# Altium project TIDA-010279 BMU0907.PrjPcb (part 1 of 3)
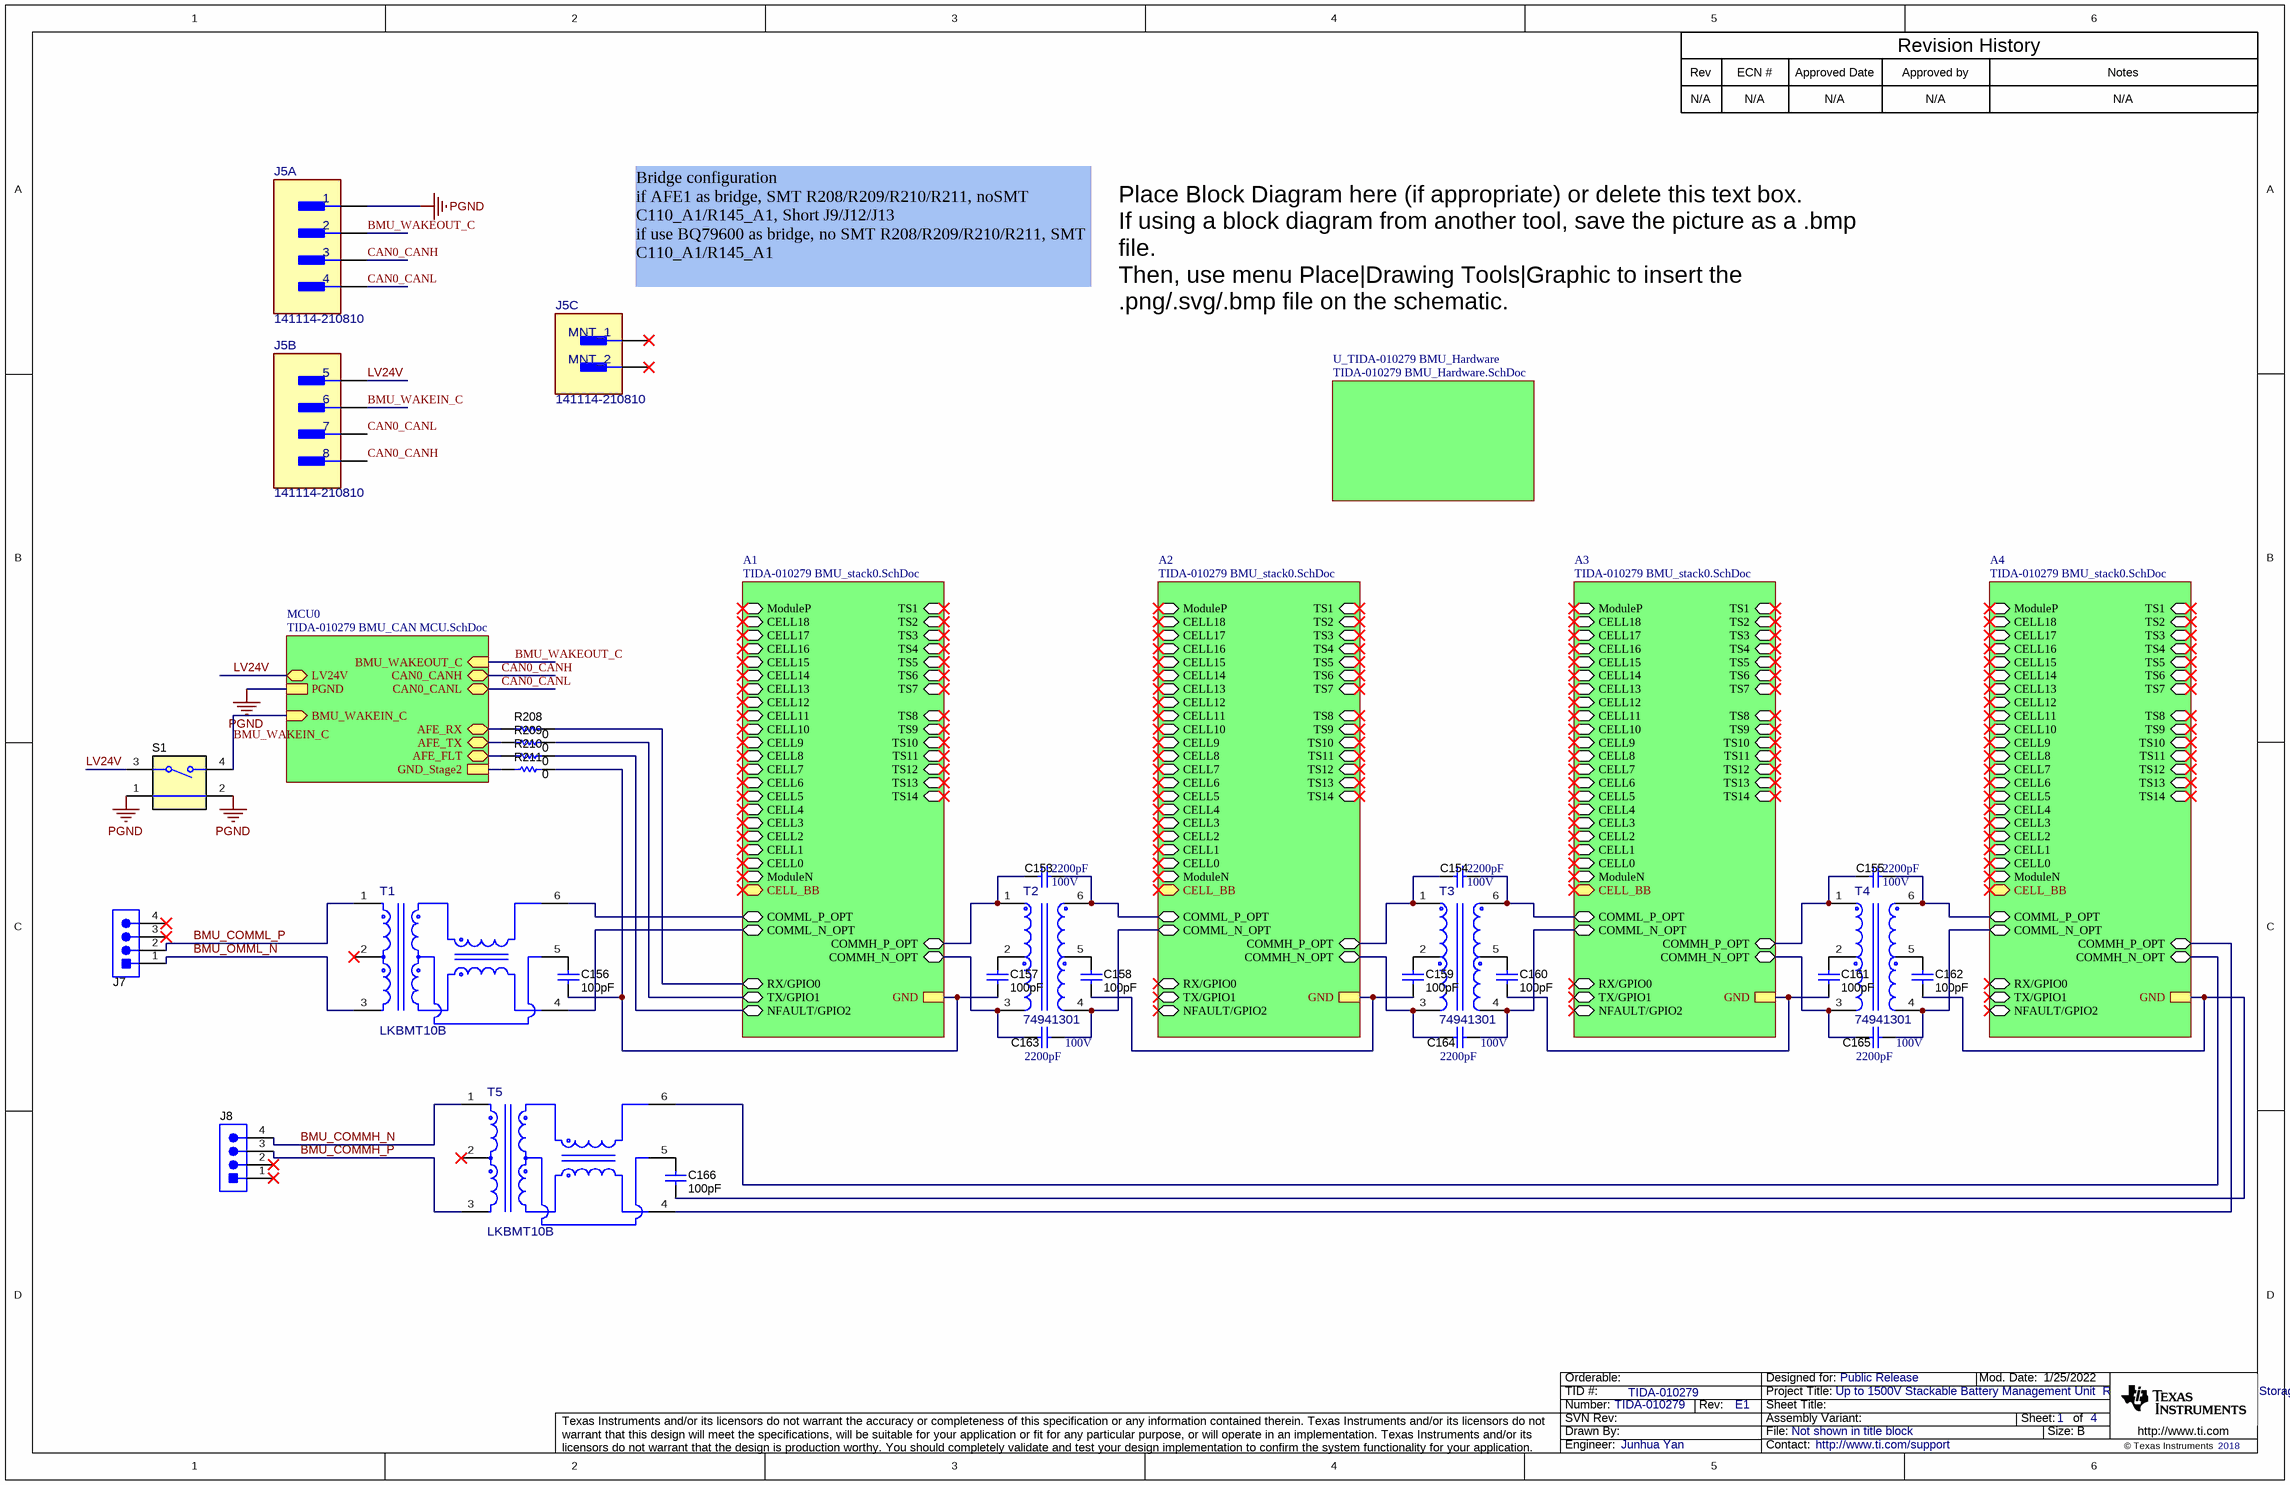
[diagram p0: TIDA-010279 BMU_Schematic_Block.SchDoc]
CopyrightYear: 2018; Orderable: N/A; PCB_Layout: Junhua Yan; PCB_Rev: E1; PRJ_Customer: Public Release; PRJ_Engineer: Junhua Yan; PRJ_Number: TIDA-010279; PRJ_Title: Up to 1500V Stackable Battery Management Unit  Reference Design for Energy Storage Systems; SCH_Rev: E1; TechSupport: http://www.ti.com/support; TID: TIDA-010279
4 sheets, 1494 parts. Net scope: hierarchical (ports join the sheet entries above them; power ports are global).
Board file: TIDA-010279 BMU0829.PcbDoc
Sheets:
  TIDA-010279 BMU_Schematic_Block.SchDoc
    A1 = TIDA-010279 BMU_stack0.SchDoc
    MCU0 = TIDA-010279 BMU_CAN MCU.SchDoc
    A2 = TIDA-010279 BMU_stack0.SchDoc
    A3 = TIDA-010279 BMU_stack0.SchDoc
    A4 = TIDA-010279 BMU_stack0.SchDoc
    U_TIDA-010279 BMU_Hardware = TIDA-010279 BMU_Hardware.SchDoc

## Sheet TIDA-010279 BMU_Schematic_Block.SchDoc
size 431 x 279 mm; Date: Not shown in title block; ApprovedBy: Not shown in title block; CheckedBy: Not shown in title block; Author: Not shown in title block; CompanyName: Not shown in title block; Engineer: Not shown in title block; Organization: Not shown in title block; Address1: Not shown in title block; Address2: Not shown in title block; Address3: Not shown in title block; Address4: Not shown in title block; DocumentNumber: 1; Revision: Use project parameter SCH_Rev; SheetNumber: 1; SheetTotal: 4; PageSetup: Record=PageOptions¦CenterHorizontal=True¦CenterVertical=True¦PrintScale=1.00¦XCorrection=1.00¦YCorrection=1.00¦PrintKind=0¦BorderSize=5000000¦LeftOffset=0¦BottomOffset=0¦Orientation=2¦PaperLength=1000¦PaperWidth=1000¦Scale=100¦PaperSource=15¦PrintQuality=600¦MediaType=1¦DitherType=10¦PaperKind=Letter¦PrintScaleMode=1

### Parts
C153  VDC_V: 100V  ValueDisplayed: 2200pF  [1206]  (hidden comment: 12061A222JAT2A)
C154  VDC_V: 100V  ValueDisplayed: 2200pF  [1206]  (hidden comment: 12061A222JAT2A)
C155  VDC_V: 100V  ValueDisplayed: 2200pF  [1206]  (hidden comment: 12061A222JAT2A)
C156  ValueDisplayed: 100pF  [0603]  (hidden comment: GCM1885C1H101JA16J)
C157  ValueDisplayed: 100pF  [0603]  (hidden comment: GCM1885C1H101JA16J)
C158  ValueDisplayed: 100pF  [0603]  (hidden comment: GCM1885C1H101JA16J)
C159  ValueDisplayed: 100pF  [0603]  (hidden comment: GCM1885C1H101JA16J)
C160  ValueDisplayed: 100pF  [0603]  (hidden comment: GCM1885C1H101JA16J)
C161  ValueDisplayed: 100pF  [0603]  (hidden comment: GCM1885C1H101JA16J)
C162  ValueDisplayed: 100pF  [0603]  (hidden comment: GCM1885C1H101JA16J)
C163  VDC_V: 100V  ValueDisplayed: 2200pF  [1206]  (hidden comment: 12061A222JAT2A)
C164  VDC_V: 100V  ValueDisplayed: 2200pF  [1206]  (hidden comment: 12061A222JAT2A)
C165  VDC_V: 100V  ValueDisplayed: 2200pF  [1206]  (hidden comment: 12061A222JAT2A)
C166  ValueDisplayed: 100pF  [0603]  (hidden comment: GCM1885C1H101JA16J)
J5  141114-210810  [FP-141114-210810_CONN_HDR16-MFG]  (parts A,B,C of 3)
J7  70551-0038  [Molex_70551-0038]  (value not drawn)
J8  70551-0038  [Molex_70551-0038]  (value not drawn)
R208  ValueDisplayed: 0  [0402]  (hidden comment: CRCW04020000Z0ED)
R209  ValueDisplayed: 0  [0402]  (hidden comment: CRCW04020000Z0ED)
R210  ValueDisplayed: 0  [0402]  (hidden comment: CRCW04020000Z0ED)
R211  ValueDisplayed: 0  [0402]  (hidden comment: CRCW04020000Z0ED)
S1  1188E-1K2-V-TR  [SW_1188E]  (value not drawn)
T1  LKBMT10B  [FP-LKBMT10B_SMT_XFRMR_27MM9_12MM5-MFG]
T2  74941301  [FP-HMU1228NL_SMT_TRANSFORMER_8MM89_10MM09-MFG]
T3  74941301  [FP-HMU1228NL_SMT_TRANSFORMER_8MM89_10MM09-MFG]
T4  74941301  [FP-HMU1228NL_SMT_TRANSFORMER_8MM89_10MM09-MFG]
T5  LKBMT10B  [FP-LKBMT10B_SMT_XFRMR_27MM9_12MM5-MFG]

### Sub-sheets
A1 = TIDA-010279 BMU_stack0.SchDoc: ModuleP (bidir), CELL9 (bidir), CELL10 (bidir), CELL11 (bidir), CELL12 (bidir), CELL13 (bidir), CELL14 (bidir), CELL15 (bidir), CELL16 (bidir), CELL8 (bidir), CELL17 (bidir), CELL18 (bidir), ModuleN (bidir), CELL1 (bidir), CELL2 (bidir), CELL3 (bidir), CELL4 (bidir), CELL5 (bidir), CELL6 (bidir), CELL7 (bidir), CELL0 (bidir), TS1 (bidir), TS2 (bidir), TS3 (bidir), TS4 (bidir), TS5 (bidir), TS6 (bidir), TS7 (bidir), TS8 (bidir), TS9 (bidir), TS10 (bidir), TS11 (bidir), TS12 (bidir), TS13 (bidir), TS14 (bidir), COMML_N_OPT (bidir), COMML_P_OPT (bidir), COMMH_N_OPT (bidir), COMMH_P_OPT (bidir), CELL_BB (bidir), GND, NFAULT/GPIO2 (bidir), TX/GPIO1 (bidir), RX/GPIO0 (bidir)
A2 = TIDA-010279 BMU_stack0.SchDoc: ModuleP (bidir), CELL9 (bidir), CELL10 (bidir), CELL11 (bidir), CELL12 (bidir), CELL13 (bidir), CELL14 (bidir), CELL15 (bidir), CELL16 (bidir), CELL8 (bidir), CELL17 (bidir), CELL18 (bidir), ModuleN (bidir), CELL1 (bidir), CELL2 (bidir), CELL3 (bidir), CELL4 (bidir), CELL5 (bidir), CELL6 (bidir), CELL7 (bidir), CELL0 (bidir), TS1 (bidir), TS2 (bidir), TS3 (bidir), TS4 (bidir), TS5 (bidir), TS6 (bidir), TS7 (bidir), TS8 (bidir), TS9 (bidir), TS10 (bidir), TS11 (bidir), TS12 (bidir), TS13 (bidir), TS14 (bidir), COMML_N_OPT (bidir), COMML_P_OPT (bidir), COMMH_N_OPT (bidir), COMMH_P_OPT (bidir), CELL_BB (bidir), GND, NFAULT/GPIO2 (bidir), TX/GPIO1 (bidir), RX/GPIO0 (bidir)
A3 = TIDA-010279 BMU_stack0.SchDoc: ModuleP (bidir), CELL9 (bidir), CELL10 (bidir), CELL11 (bidir), CELL12 (bidir), CELL13 (bidir), CELL14 (bidir), CELL15 (bidir), CELL16 (bidir), CELL8 (bidir), CELL17 (bidir), CELL18 (bidir), ModuleN (bidir), CELL1 (bidir), CELL2 (bidir), CELL3 (bidir), CELL4 (bidir), CELL5 (bidir), CELL6 (bidir), CELL7 (bidir), CELL0 (bidir), TS1 (bidir), TS2 (bidir), TS3 (bidir), TS4 (bidir), TS5 (bidir), TS6 (bidir), TS7 (bidir), TS8 (bidir), TS9 (bidir), TS10 (bidir), TS11 (bidir), TS12 (bidir), TS13 (bidir), TS14 (bidir), COMML_N_OPT (bidir), COMML_P_OPT (bidir), COMMH_N_OPT (bidir), COMMH_P_OPT (bidir), CELL_BB (bidir), GND, NFAULT/GPIO2 (bidir), TX/GPIO1 (bidir), RX/GPIO0 (bidir)
A4 = TIDA-010279 BMU_stack0.SchDoc: ModuleP (bidir), CELL9 (bidir), CELL10 (bidir), CELL11 (bidir), CELL12 (bidir), CELL13 (bidir), CELL14 (bidir), CELL15 (bidir), CELL16 (bidir), CELL8 (bidir), CELL17 (bidir), CELL18 (bidir), ModuleN (bidir), CELL1 (bidir), CELL2 (bidir), CELL3 (bidir), CELL4 (bidir), CELL5 (bidir), CELL6 (bidir), CELL7 (bidir), CELL0 (bidir), TS1 (bidir), TS2 (bidir), TS3 (bidir), TS4 (bidir), TS5 (bidir), TS6 (bidir), TS7 (bidir), TS8 (bidir), TS9 (bidir), TS10 (bidir), TS11 (bidir), TS12 (bidir), TS13 (bidir), TS14 (bidir), COMML_N_OPT (bidir), COMML_P_OPT (bidir), COMMH_N_OPT (bidir), COMMH_P_OPT (bidir), CELL_BB (bidir), GND, NFAULT/GPIO2 (bidir), TX/GPIO1 (bidir), RX/GPIO0 (bidir)
MCU0 = TIDA-010279 BMU_CAN MCU.SchDoc: CAN0_CANH (bidir), CAN0_CANL (bidir), BMU_WAKEOUT_C (in), BMU_WAKEIN_C (in), LV24V (bidir), GND_Stage2, PGND, AFE_FLT (bidir), AFE_TX (bidir), AFE_RX (bidir)
U_TIDA-010279 BMU_Hardware = TIDA-010279 BMU_Hardware.SchDoc: no entries

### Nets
GND: C156.1 C157.1 C158.1 C159.1 C160.1 C161.1 C162.1 C166.1 R211.1 ; sheet A1/GND, sheet A2/GND, sheet A3/GND, sheet A4/GND
GND_Stage2: R211.2 ; sheet MCU0/GND_Stage2
PGND: J5.1 S1.1 S1.2 ; sheet MCU0/PGND
AFE_FLT: R210.2 ; sheet MCU0/AFE_FLT
AFE_RX: R208.2 ; sheet MCU0/AFE_RX
AFE_TX: R209.2 ; sheet MCU0/AFE_TX
BMU_COMMH_N: J8.4 T5.1
BMU_COMMH_P: J8.3 T5.3
BMU_COMML_P: J7.2 T1.1
BMU_OMML_N: J7.1 T1.3
BMU_WAKEIN_C: J5.6 S1.4 ; sheet MCU0/BMU_WAKEIN_C
BMU_WAKEOUT_C: J5.2 ; sheet MCU0/BMU_WAKEOUT_C
CAN0_CANH: J5.3 J5.8 ; sheet MCU0/CAN0_CANH
CAN0_CANL: J5.4 J5.7 ; sheet MCU0/CAN0_CANL
COMMH_N_OPT: C163.1 T2.3(TD-) ; sheet A1/COMMH_N_OPT
COMMH_N_OPT: C164.1 T3.3(TD-) ; sheet A2/COMMH_N_OPT  [a separate net that carries the same name]
COMMH_N_OPT: C165.1 T4.3(TD-) ; sheet A3/COMMH_N_OPT  [a separate net that carries the same name]
COMMH_N_OPT: T5.6 ; sheet A4/COMMH_N_OPT  [a separate net that carries the same name]
COMMH_P_OPT: C153.2 T2.1(TD+) ; sheet A1/COMMH_P_OPT
COMMH_P_OPT: C154.2 T3.1(TD+) ; sheet A2/COMMH_P_OPT  [a separate net that carries the same name]
COMMH_P_OPT: C155.2 T4.1(TD+) ; sheet A3/COMMH_P_OPT  [a separate net that carries the same name]
COMMH_P_OPT: T5.4 ; sheet A4/COMMH_P_OPT  [a separate net that carries the same name]
COMML_N_OPT: C163.2 T2.4(TX-) ; sheet A2/COMML_N_OPT
COMML_N_OPT: C164.2 T3.4(TX-) ; sheet A3/COMML_N_OPT  [a separate net that carries the same name]
COMML_N_OPT: C165.2 T4.4(TX-) ; sheet A4/COMML_N_OPT  [a separate net that carries the same name]
COMML_N_OPT: T1.4 ; sheet A1/COMML_N_OPT  [a separate net that carries the same name]
COMML_P_OPT: C153.1 T2.6(TX+) ; sheet A2/COMML_P_OPT
COMML_P_OPT: C154.1 T3.6(TX+) ; sheet A3/COMML_P_OPT  [a separate net that carries the same name]
COMML_P_OPT: C155.1 T4.6(TX+) ; sheet A4/COMML_P_OPT  [a separate net that carries the same name]
COMML_P_OPT: T1.6 ; sheet A1/COMML_P_OPT  [a separate net that carries the same name]
LV24V: J5.5 S1.3 ; sheet MCU0/LV24V
NFAULT/GPIO2: R210.1 ; sheet A1/NFAULT/GPIO2
RX/GPIO0: R208.1 ; sheet A1/RX/GPIO0
TX/GPIO1: R209.1 ; sheet A1/TX/GPIO1
NetC156_2: C156.2 T1.5
NetC157_2: C157.2 T2.2(TCT)
NetC158_2: C158.2 T2.5(CMT)
NetC159_2: C159.2 T3.2(TCT)
NetC160_2: C160.2 T3.5(CMT)
NetC161_2: C161.2 T4.2(TCT)
NetC162_2: C162.2 T4.5(CMT)
NetC166_2: C166.2 T5.5

Not connected (* = marked no-connect by the designer): J5 9(MNT_1)* 10(MNT_2)*; J7 3* 4*; J8 1* 2*; T1 2*; T5 2*

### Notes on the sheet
- Rev
- N/A
- ECN #
- Approved Date
- Approved by
- Revision History
- Notes
- Bridge configuration
  if AFE1 as bridge, SMT R208/R209/R210/R211, noSMT C110_A1/R145_A1, Short J9/J12/J13
  if use BQ79600 as bridge, no SMT R208/R209/R210/R211, SMT C110_A1/R145_A1
- Place Block Diagram here (if appropriate) or delete this text box.
  If using a block diagram from another tool, save the picture as a .bmp file.
  Then, use menu Place|Drawing Tools|Graphic to insert the .png/.svg/.bmp file on the schematic.

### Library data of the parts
C153-C155 C163-C165 = CMP-0008473-2: CAP, CERM, 2200 pF, 100 V, +/- 5%, C0G/NP0, 1206; Manufacturer: AVX; TaMin_C: -55°C; ESR_ohm: 1.73d; Polarized: N; SizeAreaWB_mm2: 10.92; Value1: 0.173 ohm; U/M: EA; Value: 2200pF; TaMax_C: 125°C; SizeZ_mm: 1.35; SizeX_mm: 3.2; SizeY_mm: 1.6; SizeArea_mm2: 5.12; Cap_F: 2.2nF; AEC Category: Q200
C156-C162 C166 = CMP-0750041-1: CAP, CERM, 100 pF, 50 V,+/- 5%, C0G/NP0, AEC-Q200 Grade 1, 0603; Manufacturer: MuRata; TaMin_C: -55°C; Polarized: N; SizeAreaWB_mm2: 4.68; U/M: EA; Value: 100pF; TaMax_C: 125°C; SizeZ_mm: 1; SizeX_mm: 1.6; SizeY_mm: 0.8; Value2: 50V; SizeArea_mm2: 1.28; AEC Qualified: Y; AEC Category: Q200
J5 = CMP-0091530-1: 2.00mm R/A SMT WAFER 8PIN KEY-A WITH CPA FEATURE; Manufacturer: BEIJIDA ELECTRONICS TECHNOLOGY; ContactFinish: Tin,Nickel; Current_A: 3A; Row_Count: 2; Voltage_V: 60V; AEC Grade: NA; AEC Qualified: No; Conn Gender: Male; Conn Orientation: Right Angle; DUT-Pitch_mm: 2mm; SizeZ_mm: 9.6mm
J7 J8 = CMP-0055239-1: Header(shrouded), 2.54mm, 4x1, R/A, Gold, TH; Manufacturer: Molex; CNHeader: FALSE; Current_A: 3A; Green_Lifecycle: Active; Shrouded: Y; Gender: Male; Green_REACh: Passed; Voltage_V: 250V; Row_Count: 1; Pitch_mm: 2.54
R208-R211 = CMP-0026822-3: RES, 0, 5%, 0.063 W, AEC-Q200 Grade 0, 0402; Manufacturer: Vishay-Dale; Power_W: 63mW; TempCo: 200 ppm/C; Value_Code: 0000; Value: 0; EIA_Code: E24; SizeX_mm: 1; SizeY_mm: 0.5; SizeZ_mm: 0.6; Value2: 0.063W; AEC Qualified: Y; VDC_V: 50V; AEC Category: Q200
S1 = CMP-0002328-1: Switch, SPST, 0.05 A, 12 VDC, SMD; Manufacturer: Diptronics; CurrentRating_mA: 50A; PositionCount: 1; SizeX_mm: 7.8; SizeY_mm: 3.5; SizeArea_mm2: 27.3; VDC_V: 12V; SizeAreaWB_mm2: 53.9
T1 T5 = CMP-0122349-1: SMD BMS Transformer; Manufacturer: LineKey Technology; DCR_ohm: 0.8; Ind_H: 300µH; Ns1toNp: 1:1; Rsec1_ohm: 1; SizeZ_mm: 9.5mm; AEC Qualified: Yes; AEC Grade: Grade 1; Insertion Loss: -0.5dB; Return Loss: -20dB; Voltage_Isolation_Vrms: 5000VDC
T2-T4 = CMP-0086619-1: BMS TRANSFORMER; Manufacturer: Wurth Elektronik; Ns1toNp: 1:1; Ind_H: 150µH; SizeZ_mm: 6.85mm; AEC Grade: Grade 1; AEC Qualified: Yes

## Sheet TIDA-010279 BMU_stack0.SchDoc
size 558 x 431 mm; Date: Not shown in title block; ApprovedBy: Not shown in title block; CheckedBy: Not shown in title block; Author: Not shown in title block; CompanyName: Not shown in title block; Engineer: Not shown in title block; Organization: Not shown in title block; Address1: Not shown in title block; Address2: Not shown in title block; Address3: Not shown in title block; Address4: Not shown in title block; DocumentNumber: 2; Revision: Use project parameter SCH_Rev; SheetNumber: 2; SheetTotal: 4; PageSetup: Record=PageOptions¦CenterHorizontal=True¦CenterVertical=True¦PrintScale=1.00¦XCorrection=1.00¦YCorrection=1.00¦PrintKind=0¦BorderSize=5000000¦LeftOffset=0¦BottomOffset=0¦Orientation=2¦PaperLength=1000¦PaperWidth=1000¦Scale=100¦PaperSource=15¦PrintQuality=600¦MediaType=1¦DitherType=10¦PaperKind=Letter¦PrintScaleMode=1
Used 4 times, as channels A1, A2, A3, A4. Parts and nets are listed once, with the designators drawn on the sheet.
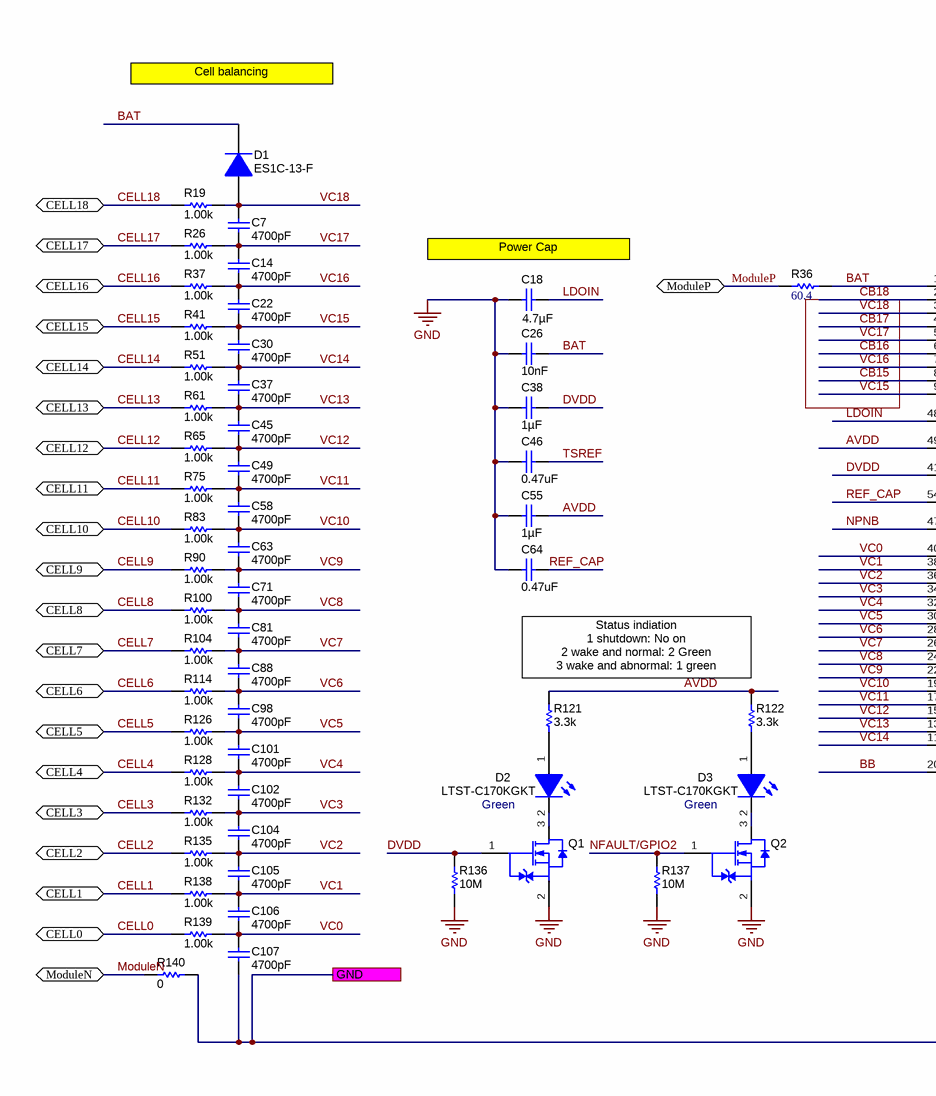
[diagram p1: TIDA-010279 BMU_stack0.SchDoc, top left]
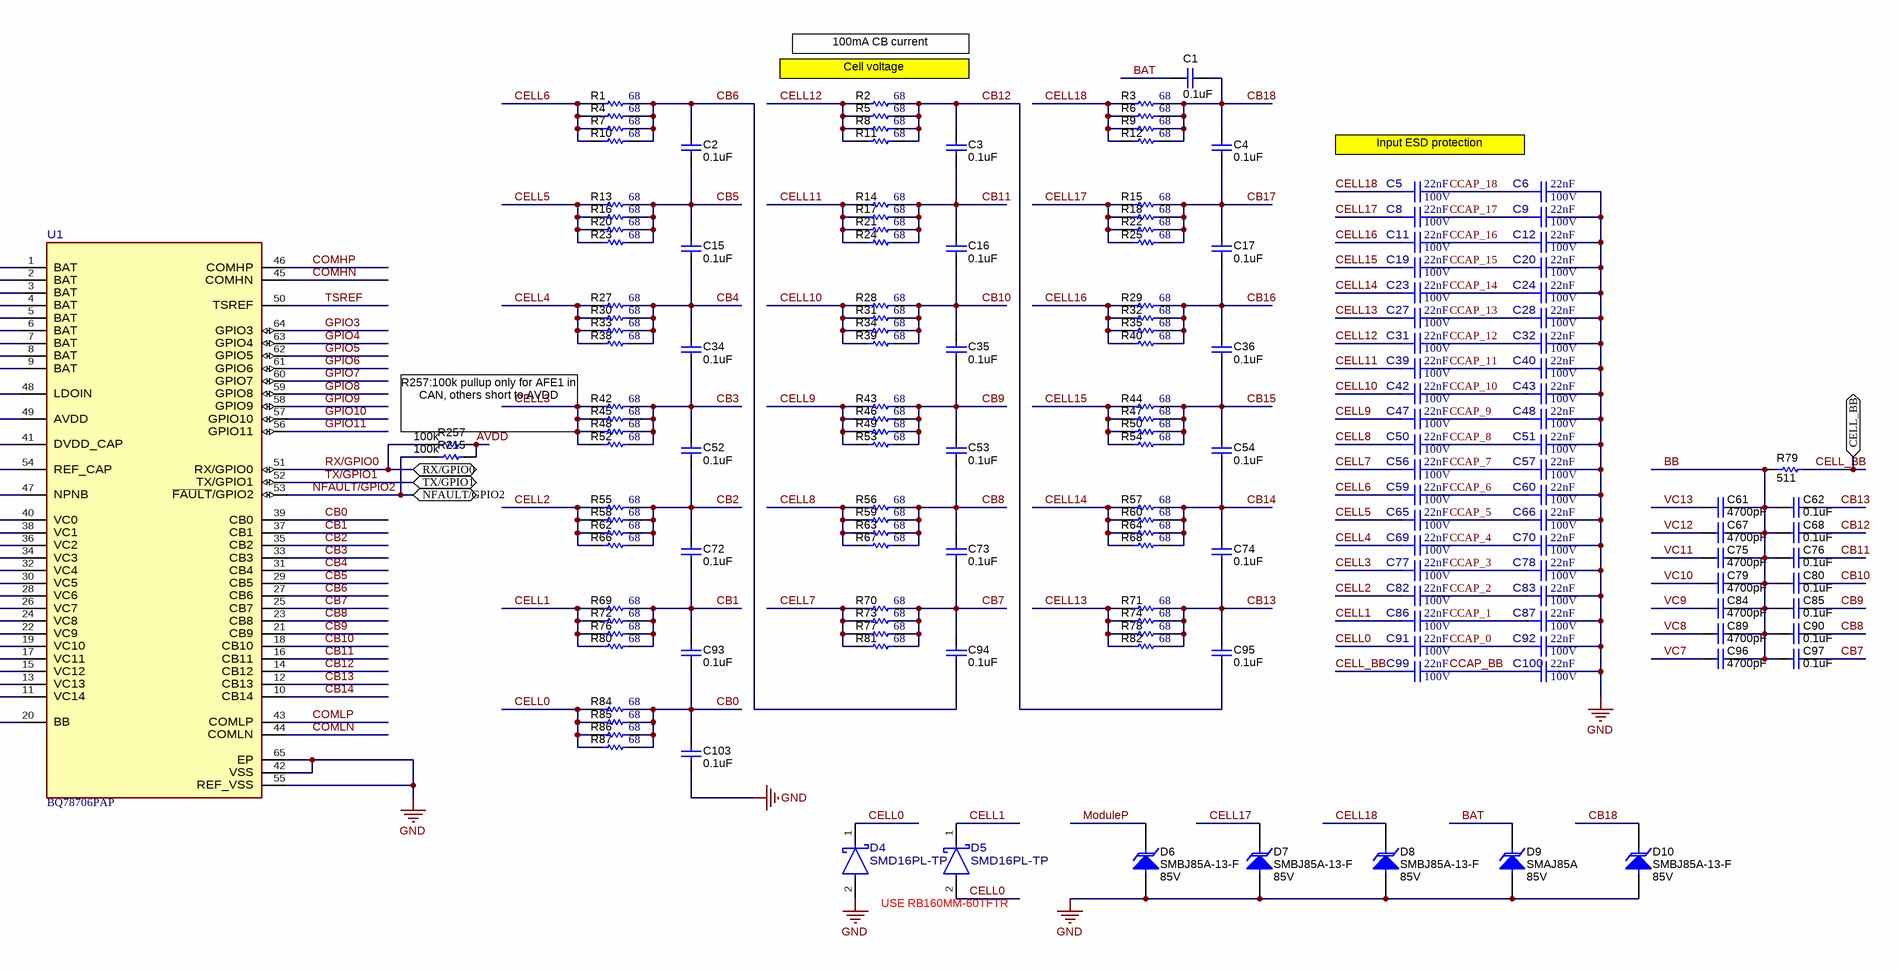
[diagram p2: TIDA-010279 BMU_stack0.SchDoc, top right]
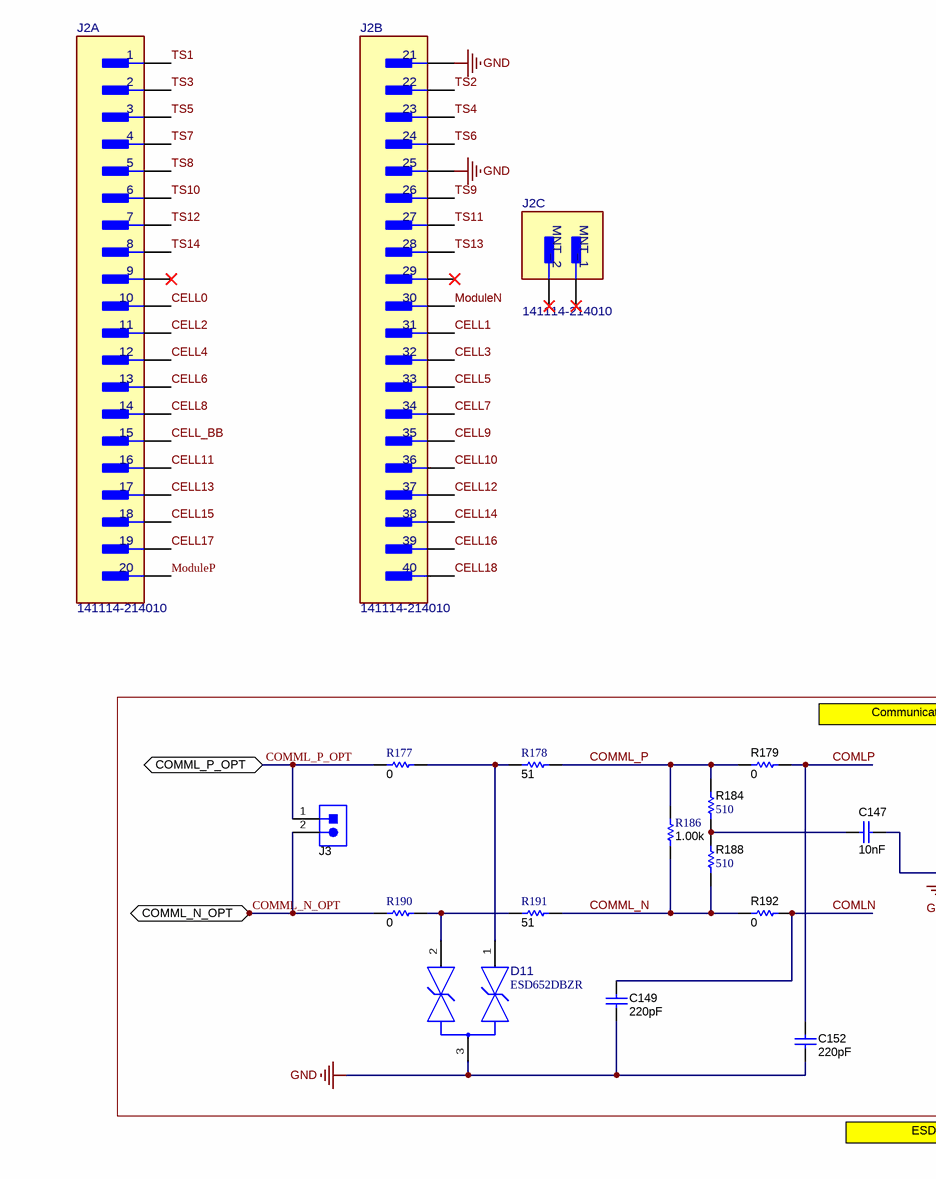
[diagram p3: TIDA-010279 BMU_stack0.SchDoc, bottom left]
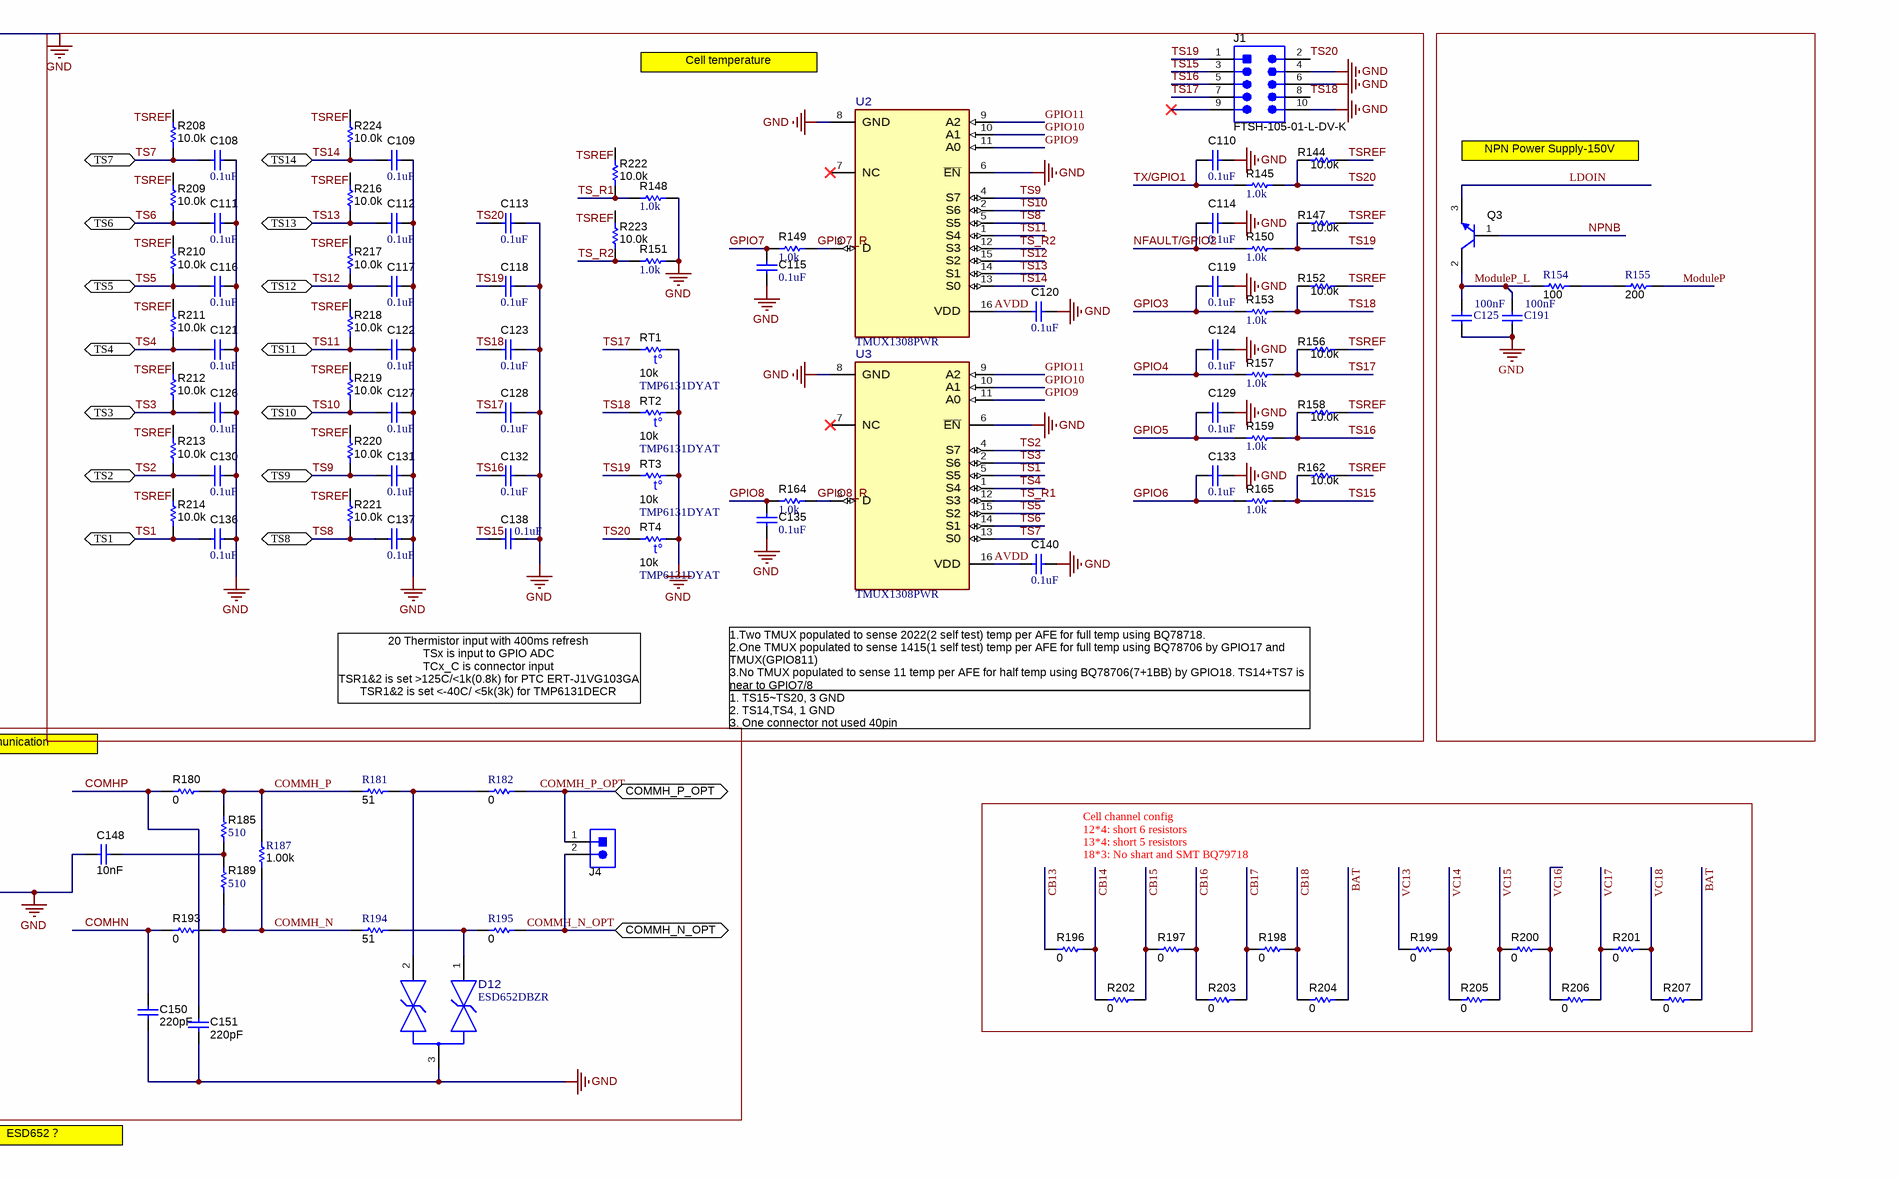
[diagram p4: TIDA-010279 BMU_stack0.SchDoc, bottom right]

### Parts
C1  ValueDisplayed: 0.1uF  [0402]  (hidden comment: GCM155R71H104KE02D)
C2  ValueDisplayed: 0.1uF  [0402]  (hidden comment: GCM155R71H104KE02D)
C3  ValueDisplayed: 0.1uF  [0402]  (hidden comment: GCM155R71H104KE02D)
C4  ValueDisplayed: 0.1uF  [0402]  (hidden comment: GCM155R71H104KE02D)
C5  VDC_V: 100V  Cap_F: 22nF  [FP-CGA3E2X7R2A223K080AA_0603-MFG]  (hidden comment: CGA3E2X7R2A223K080AA)
C6  VDC_V: 100V  Cap_F: 22nF  [FP-CGA3E2X7R2A223K080AA_0603-MFG]  (hidden comment: CGA3E2X7R2A223K080AA)
C7  ValueDisplayed: 4700pF  [0402]  (hidden comment: GCM155R71H472KA37D)
C8  VDC_V: 100V  Cap_F: 22nF  [FP-CGA3E2X7R2A223K080AA_0603-MFG]  (hidden comment: CGA3E2X7R2A223K080AA)
C9  VDC_V: 100V  Cap_F: 22nF  [FP-CGA3E2X7R2A223K080AA_0603-MFG]  (hidden comment: CGA3E2X7R2A223K080AA)
C11  VDC_V: 100V  Cap_F: 22nF  [FP-CGA3E2X7R2A223K080AA_0603-MFG]  (hidden comment: CGA3E2X7R2A223K080AA)
C12  VDC_V: 100V  Cap_F: 22nF  [FP-CGA3E2X7R2A223K080AA_0603-MFG]  (hidden comment: CGA3E2X7R2A223K080AA)
C14  ValueDisplayed: 4700pF  [0402]  (hidden comment: GCM155R71H472KA37D)
C15  ValueDisplayed: 0.1uF  [0402]  (hidden comment: GCM155R71H104KE02D)
C16  ValueDisplayed: 0.1uF  [0402]  (hidden comment: GCM155R71H104KE02D)
C17  ValueDisplayed: 0.1uF  [0402]  (hidden comment: GCM155R71H104KE02D)
C18  Cap_F: 4.7µF  [0805_HV]  (hidden comment: C0805C475J8RACAUTO)
C19  VDC_V: 100V  Cap_F: 22nF  [FP-CGA3E2X7R2A223K080AA_0603-MFG]  (hidden comment: CGA3E2X7R2A223K080AA)
C20  VDC_V: 100V  Cap_F: 22nF  [FP-CGA3E2X7R2A223K080AA_0603-MFG]  (hidden comment: CGA3E2X7R2A223K080AA)
C22  ValueDisplayed: 4700pF  [0402]  (hidden comment: GCM155R71H472KA37D)
C23  VDC_V: 100V  Cap_F: 22nF  [FP-CGA3E2X7R2A223K080AA_0603-MFG]  (hidden comment: CGA3E2X7R2A223K080AA)
C24  VDC_V: 100V  Cap_F: 22nF  [FP-CGA3E2X7R2A223K080AA_0603-MFG]  (hidden comment: CGA3E2X7R2A223K080AA)
C26  Cap_F: 10nF  [0603_HV]  (hidden comment: GCM188R72A103KA37J)
C27  VDC_V: 100V  Cap_F: 22nF  [FP-CGA3E2X7R2A223K080AA_0603-MFG]  (hidden comment: CGA3E2X7R2A223K080AA)
C28  VDC_V: 100V  Cap_F: 22nF  [FP-CGA3E2X7R2A223K080AA_0603-MFG]  (hidden comment: CGA3E2X7R2A223K080AA)
C30  ValueDisplayed: 4700pF  [0402]  (hidden comment: GCM155R71H472KA37D)
C31  VDC_V: 100V  Cap_F: 22nF  [FP-CGA3E2X7R2A223K080AA_0603-MFG]  (hidden comment: CGA3E2X7R2A223K080AA)
C32  VDC_V: 100V  Cap_F: 22nF  [FP-CGA3E2X7R2A223K080AA_0603-MFG]  (hidden comment: CGA3E2X7R2A223K080AA)
C34  ValueDisplayed: 0.1uF  [0402]  (hidden comment: GCM155R71H104KE02D)
C35  ValueDisplayed: 0.1uF  [0402]  (hidden comment: GCM155R71H104KE02D)
C36  ValueDisplayed: 0.1uF  [0402]  (hidden comment: GCM155R71H104KE02D)
C37  ValueDisplayed: 4700pF  [0402]  (hidden comment: GCM155R71H472KA37D)
C38  Cap_F: 1µF  [0603]  (hidden comment: GCM188R71C105KA64D)
C39  VDC_V: 100V  Cap_F: 22nF  [FP-CGA3E2X7R2A223K080AA_0603-MFG]  (hidden comment: CGA3E2X7R2A223K080AA)
C40  VDC_V: 100V  Cap_F: 22nF  [FP-CGA3E2X7R2A223K080AA_0603-MFG]  (hidden comment: CGA3E2X7R2A223K080AA)
C42  VDC_V: 100V  Cap_F: 22nF  [FP-CGA3E2X7R2A223K080AA_0603-MFG]  (hidden comment: CGA3E2X7R2A223K080AA)
C43  VDC_V: 100V  Cap_F: 22nF  [FP-CGA3E2X7R2A223K080AA_0603-MFG]  (hidden comment: CGA3E2X7R2A223K080AA)
C45  ValueDisplayed: 4700pF  [0402]  (hidden comment: GCM155R71H472KA37D)
C46  ValueDisplayed: 0.47uF  [0603]  (hidden comment: GCM188R71C474KA55D)
C47  VDC_V: 100V  Cap_F: 22nF  [FP-CGA3E2X7R2A223K080AA_0603-MFG]  (hidden comment: CGA3E2X7R2A223K080AA)
C48  VDC_V: 100V  Cap_F: 22nF  [FP-CGA3E2X7R2A223K080AA_0603-MFG]  (hidden comment: CGA3E2X7R2A223K080AA)
C49  ValueDisplayed: 4700pF  [0402]  (hidden comment: GCM155R71H472KA37D)
C50  VDC_V: 100V  Cap_F: 22nF  [FP-CGA3E2X7R2A223K080AA_0603-MFG]  (hidden comment: CGA3E2X7R2A223K080AA)
C51  VDC_V: 100V  Cap_F: 22nF  [FP-CGA3E2X7R2A223K080AA_0603-MFG]  (hidden comment: CGA3E2X7R2A223K080AA)
C52  ValueDisplayed: 0.1uF  [0402]  (hidden comment: GCM155R71H104KE02D)
C53  ValueDisplayed: 0.1uF  [0402]  (hidden comment: GCM155R71H104KE02D)
C54  ValueDisplayed: 0.1uF  [0402]  (hidden comment: GCM155R71H104KE02D)
C55  Cap_F: 1µF  [0603]  (hidden comment: GCM188R71C105KA64D)
C56  VDC_V: 100V  Cap_F: 22nF  [FP-CGA3E2X7R2A223K080AA_0603-MFG]  (hidden comment: CGA3E2X7R2A223K080AA)
C57  VDC_V: 100V  Cap_F: 22nF  [FP-CGA3E2X7R2A223K080AA_0603-MFG]  (hidden comment: CGA3E2X7R2A223K080AA)
C58  ValueDisplayed: 4700pF  [0402]  (hidden comment: GCM155R71H472KA37D)
C59  VDC_V: 100V  Cap_F: 22nF  [FP-CGA3E2X7R2A223K080AA_0603-MFG]  (hidden comment: CGA3E2X7R2A223K080AA)
C60  VDC_V: 100V  Cap_F: 22nF  [FP-CGA3E2X7R2A223K080AA_0603-MFG]  (hidden comment: CGA3E2X7R2A223K080AA)
C61  ValueDisplayed: 4700pF  [0402]  (hidden comment: GCM155R71H472KA37D)
C62  ValueDisplayed: 0.1uF  [0402]  (hidden comment: GCM155R71H104KE02D)
C63  ValueDisplayed: 4700pF  [0402]  (hidden comment: GCM155R71H472KA37D)
C64  ValueDisplayed: 0.47uF  [0603]  (hidden comment: GCM188R71C474KA55D)
C65  VDC_V: 100V  Cap_F: 22nF  [FP-CGA3E2X7R2A223K080AA_0603-MFG]  (hidden comment: CGA3E2X7R2A223K080AA)
C66  VDC_V: 100V  Cap_F: 22nF  [FP-CGA3E2X7R2A223K080AA_0603-MFG]  (hidden comment: CGA3E2X7R2A223K080AA)
C67  ValueDisplayed: 4700pF  [0402]  (hidden comment: GCM155R71H472KA37D)
C68  ValueDisplayed: 0.1uF  [0402]  (hidden comment: GCM155R71H104KE02D)
C69  VDC_V: 100V  Cap_F: 22nF  [FP-CGA3E2X7R2A223K080AA_0603-MFG]  (hidden comment: CGA3E2X7R2A223K080AA)
C70  VDC_V: 100V  Cap_F: 22nF  [FP-CGA3E2X7R2A223K080AA_0603-MFG]  (hidden comment: CGA3E2X7R2A223K080AA)
C71  ValueDisplayed: 4700pF  [0402]  (hidden comment: GCM155R71H472KA37D)
C72  ValueDisplayed: 0.1uF  [0402]  (hidden comment: GCM155R71H104KE02D)
C73  ValueDisplayed: 0.1uF  [0402]  (hidden comment: GCM155R71H104KE02D)
C74  ValueDisplayed: 0.1uF  [0402]  (hidden comment: GCM155R71H104KE02D)
C75  ValueDisplayed: 4700pF  [0402]  (hidden comment: GCM155R71H472KA37D)
C76  ValueDisplayed: 0.1uF  [0402]  (hidden comment: GCM155R71H104KE02D)
C77  VDC_V: 100V  Cap_F: 22nF  [FP-CGA3E2X7R2A223K080AA_0603-MFG]  (hidden comment: CGA3E2X7R2A223K080AA)
C78  VDC_V: 100V  Cap_F: 22nF  [FP-CGA3E2X7R2A223K080AA_0603-MFG]  (hidden comment: CGA3E2X7R2A223K080AA)
C79  ValueDisplayed: 4700pF  [0402]  (hidden comment: GCM155R71H472KA37D)
C80  ValueDisplayed: 0.1uF  [0402]  (hidden comment: GCM155R71H104KE02D)
C81  ValueDisplayed: 4700pF  [0402]  (hidden comment: GCM155R71H472KA37D)
C82  VDC_V: 100V  Cap_F: 22nF  [FP-CGA3E2X7R2A223K080AA_0603-MFG]  (hidden comment: CGA3E2X7R2A223K080AA)
C83  VDC_V: 100V  Cap_F: 22nF  [FP-CGA3E2X7R2A223K080AA_0603-MFG]  (hidden comment: CGA3E2X7R2A223K080AA)
C84  ValueDisplayed: 4700pF  [0402]  (hidden comment: GCM155R71H472KA37D)
C85  ValueDisplayed: 0.1uF  [0402]  (hidden comment: GCM155R71H104KE02D)
C86  VDC_V: 100V  Cap_F: 22nF  [FP-CGA3E2X7R2A223K080AA_0603-MFG]  (hidden comment: CGA3E2X7R2A223K080AA)
C87  VDC_V: 100V  Cap_F: 22nF  [FP-CGA3E2X7R2A223K080AA_0603-MFG]  (hidden comment: CGA3E2X7R2A223K080AA)
C88  ValueDisplayed: 4700pF  [0402]  (hidden comment: GCM155R71H472KA37D)
C89  ValueDisplayed: 4700pF  [0402]  (hidden comment: GCM155R71H472KA37D)
C90  ValueDisplayed: 0.1uF  [0402]  (hidden comment: GCM155R71H104KE02D)
C91  VDC_V: 100V  Cap_F: 22nF  [FP-CGA3E2X7R2A223K080AA_0603-MFG]  (hidden comment: CGA3E2X7R2A223K080AA)
C92  VDC_V: 100V  Cap_F: 22nF  [FP-CGA3E2X7R2A223K080AA_0603-MFG]  (hidden comment: CGA3E2X7R2A223K080AA)
C93  ValueDisplayed: 0.1uF  [0402]  (hidden comment: GCM155R71H104KE02D)
C94  ValueDisplayed: 0.1uF  [0402]  (hidden comment: GCM155R71H104KE02D)
C95  ValueDisplayed: 0.1uF  [0402]  (hidden comment: GCM155R71H104KE02D)
C96  ValueDisplayed: 4700pF  [0402]  (hidden comment: GCM155R71H472KA37D)
C97  ValueDisplayed: 0.1uF  [0402]  (hidden comment: GCM155R71H104KE02D)
C98  ValueDisplayed: 4700pF  [0402]  (hidden comment: GCM155R71H472KA37D)
C99  VDC_V: 100V  Cap_F: 22nF  [FP-CGA3E2X7R2A223K080AA_0603-MFG]  (hidden comment: CGA3E2X7R2A223K080AA)
C100  VDC_V: 100V  Cap_F: 22nF  [FP-CGA3E2X7R2A223K080AA_0603-MFG]  (hidden comment: CGA3E2X7R2A223K080AA)
C101  ValueDisplayed: 4700pF  [0402]  (hidden comment: GCM155R71H472KA37D)
C102  ValueDisplayed: 4700pF  [0402]  (hidden comment: GCM155R71H472KA37D)
C103  ValueDisplayed: 0.1uF  [0402]  (hidden comment: GCM155R71H104KE02D)
C104  ValueDisplayed: 4700pF  [0402]  (hidden comment: GCM155R71H472KA37D)
C105  ValueDisplayed: 4700pF  [0402]  (hidden comment: GCM155R71H472KA37D)
C106  ValueDisplayed: 4700pF  [0402]  (hidden comment: GCM155R71H472KA37D)
C107  ValueDisplayed: 4700pF  [0402]  (hidden comment: GCM155R71H472KA37D)
C108  ValueDisplayed: 0.1uF  [0402]  (hidden comment: GCM155R71H104KE02D)
C109  ValueDisplayed: 0.1uF  [0402]  (hidden comment: GCM155R71H104KE02D)
C110  ValueDisplayed: 0.1uF  [0402]  (hidden comment: GCM155R71H104KE02D)
C111  ValueDisplayed: 0.1uF  [0402]  (hidden comment: GCM155R71H104KE02D)
C112  ValueDisplayed: 0.1uF  [0402]  (hidden comment: GCM155R71H104KE02D)
C113  ValueDisplayed: 0.1uF  [0402]  (hidden comment: GCM155R71H104KE02D)
C114  ValueDisplayed: 0.1uF  [0402]  (hidden comment: GCM155R71H104KE02D)
C115  ValueDisplayed: 0.1uF  [0402]  (hidden comment: GCM155R71H104KE02D)
C116  ValueDisplayed: 0.1uF  [0402]  (hidden comment: GCM155R71H104KE02D)
C117  ValueDisplayed: 0.1uF  [0402]  (hidden comment: GCM155R71H104KE02D)
C118  ValueDisplayed: 0.1uF  [0402]  (hidden comment: GCM155R71H104KE02D)
C119  ValueDisplayed: 0.1uF  [0402]  (hidden comment: GCM155R71H104KE02D)
C120  ValueDisplayed: 0.1uF  [0402]  (hidden comment: GCM155R71H104KE02D)
C121  ValueDisplayed: 0.1uF  [0402]  (hidden comment: GCM155R71H104KE02D)
C122  ValueDisplayed: 0.1uF  [0402]  (hidden comment: GCM155R71H104KE02D)
C123  ValueDisplayed: 0.1uF  [0402]  (hidden comment: GCM155R71H104KE02D)
C124  ValueDisplayed: 0.1uF  [0402]  (hidden comment: GCM155R71H104KE02D)
C125  Cap_F: 100nF  [WCAP-CSGP_1206_L3.2W1.6H1.25]  (hidden comment: 885012208118)
C126  ValueDisplayed: 0.1uF  [0402]  (hidden comment: GCM155R71H104KE02D)
C127  ValueDisplayed: 0.1uF  [0402]  (hidden comment: GCM155R71H104KE02D)
C128  ValueDisplayed: 0.1uF  [0402]  (hidden comment: GCM155R71H104KE02D)
C129  ValueDisplayed: 0.1uF  [0402]  (hidden comment: GCM155R71H104KE02D)
C130  ValueDisplayed: 0.1uF  [0402]  (hidden comment: GCM155R71H104KE02D)
C131  ValueDisplayed: 0.1uF  [0402]  (hidden comment: GCM155R71H104KE02D)
C132  ValueDisplayed: 0.1uF  [0402]  (hidden comment: GCM155R71H104KE02D)
C133  ValueDisplayed: 0.1uF  [0402]  (hidden comment: GCM155R71H104KE02D)
C135  ValueDisplayed: 0.1uF  [0402]  (hidden comment: GCM155R71H104KE02D)
C136  ValueDisplayed: 0.1uF  [0402]  (hidden comment: GCM155R71H104KE02D)
C137  ValueDisplayed: 0.1uF  [0402]  (hidden comment: GCM155R71H104KE02D)
C138  ValueDisplayed: 0.1uF  [0402]  (hidden comment: GCM155R71H104KE02D)
C140  ValueDisplayed: 0.1uF  [0402]  (hidden comment: GCM155R71H104KE02D)
C147  Cap_F: 10nF  [0603]  (hidden comment: GCM188R71H103KA37D)
C148  Cap_F: 10nF  [0603]  (hidden comment: GCM188R71H103KA37D)
C149  Cap_F: 220pF  [0603]  (hidden comment: CL10B221JB8NNNC)
C150  Cap_F: 220pF  [0603]  (hidden comment: CL10B221JB8NNNC)
C151  Cap_F: 220pF  [0603]  (hidden comment: CL10B221JB8NNNC)
C152  Cap_F: 220pF  [0603]  (hidden comment: CL10B221JB8NNNC)
C191  Cap_F: 100nF  [WCAP-CSGP_1206_L3.2W1.6H1.25]  (hidden comment: 885012208118)
D1  ES1C-13-F  [SMA]
D2  LTST-C170KGKT  value Green  [LTST-C170KGKT_Green]
D3  LTST-C170KGKT  value Green  [LTST-C170KGKT_Green]
D4  SMD16PL-TP  [FP-SMD16PL-TP_SOD123FL-MFG]
D5  SMD16PL-TP  [FP-SMD16PL-TP_SOD123FL-MFG]
D6  SMBJ85A-13-F  value 85V  [SMB]
D7  SMBJ85A-13-F  value 85V  [SMB]
D8  SMBJ85A-13-F  value 85V  [SMB]
D9  SMAJ85A  value 85V  [SMA]
D10  SMBJ85A-13-F  value 85V  [SMB]
D11  ESD652DBZR  [DBZ0003A-MFG]
D12  ESD652DBZR  [DBZ0003A-MFG]
J1  FTSH-105-01-L-DV-K  [Samtec_FTSH-105-01-x-DV-K]
J2  141114-214010  [FP-141114-214010_HDR40-MFG]  (parts A,B,C of 3)
J3  PEC02SAAN  [CONN_PEC02SAAN]  (value not drawn)
J4  PEC02SAAN  [CONN_PEC02SAAN]  (value not drawn)
Q1  RE1C002UNTCL  [SC-89]  (value not drawn)
Q2  RE1C002UNTCL  [SC-89]  (value not drawn)
Q3  CMP-0000504-4  [DPAK]  (value not drawn)
R1  ValueDisplayed: 68  [0805_HV]  (hidden comment: HPCR0805J68R0KT)
R2  ValueDisplayed: 68  [0805_HV]  (hidden comment: HPCR0805J68R0KT)
R3  ValueDisplayed: 68  [0805_HV]  (hidden comment: HPCR0805J68R0KT)
R4  ValueDisplayed: 68  [0805_HV]  (hidden comment: HPCR0805J68R0KT)
R5  ValueDisplayed: 68  [0805_HV]  (hidden comment: HPCR0805J68R0KT)
R6  ValueDisplayed: 68  [0805_HV]  (hidden comment: HPCR0805J68R0KT)
R7  ValueDisplayed: 68  [0805_HV]  (hidden comment: HPCR0805J68R0KT)
R8  ValueDisplayed: 68  [0805_HV]  (hidden comment: HPCR0805J68R0KT)
R9  ValueDisplayed: 68  [0805_HV]  (hidden comment: HPCR0805J68R0KT)
R10  ValueDisplayed: 68  [0805_HV]  (hidden comment: HPCR0805J68R0KT)
R11  ValueDisplayed: 68  [0805_HV]  (hidden comment: HPCR0805J68R0KT)
R12  ValueDisplayed: 68  [0805_HV]  (hidden comment: HPCR0805J68R0KT)
R13  ValueDisplayed: 68  [0805_HV]  (hidden comment: HPCR0805J68R0KT)
R14  ValueDisplayed: 68  [0805_HV]  (hidden comment: HPCR0805J68R0KT)
R15  ValueDisplayed: 68  [0805_HV]  (hidden comment: HPCR0805J68R0KT)
R16  ValueDisplayed: 68  [0805_HV]  (hidden comment: HPCR0805J68R0KT)
R17  ValueDisplayed: 68  [0805_HV]  (hidden comment: HPCR0805J68R0KT)
R18  ValueDisplayed: 68  [0805_HV]  (hidden comment: HPCR0805J68R0KT)
R19  ValueDisplayed: 1.00k  [0402]  (hidden comment: CRCW04021K00FKED)
R20  ValueDisplayed: 68  [0805_HV]  (hidden comment: HPCR0805J68R0KT)
R21  ValueDisplayed: 68  [0805_HV]  (hidden comment: HPCR0805J68R0KT)
R22  ValueDisplayed: 68  [0805_HV]  (hidden comment: HPCR0805J68R0KT)
R23  ValueDisplayed: 68  [0805_HV]  (hidden comment: HPCR0805J68R0KT)
R24  ValueDisplayed: 68  [0805_HV]  (hidden comment: HPCR0805J68R0KT)
R25  ValueDisplayed: 68  [0805_HV]  (hidden comment: HPCR0805J68R0KT)
R26  ValueDisplayed: 1.00k  [0402]  (hidden comment: CRCW04021K00FKED)
R27  ValueDisplayed: 68  [0805_HV]  (hidden comment: HPCR0805J68R0KT)
R28  ValueDisplayed: 68  [0805_HV]  (hidden comment: HPCR0805J68R0KT)
R29  ValueDisplayed: 68  [0805_HV]  (hidden comment: HPCR0805J68R0KT)
R30  ValueDisplayed: 68  [0805_HV]  (hidden comment: HPCR0805J68R0KT)
R31  ValueDisplayed: 68  [0805_HV]  (hidden comment: HPCR0805J68R0KT)
R32  ValueDisplayed: 68  [0805_HV]  (hidden comment: HPCR0805J68R0KT)
R33  ValueDisplayed: 68  [0805_HV]  (hidden comment: HPCR0805J68R0KT)
R34  ValueDisplayed: 68  [0805_HV]  (hidden comment: HPCR0805J68R0KT)
R35  ValueDisplayed: 68  [0805_HV]  (hidden comment: HPCR0805J68R0KT)
R36  ValueDisplayed: 60.4  [0805_HV]  (hidden comment: CRCW080560R4FKEA)
R37  ValueDisplayed: 1.00k  [0402]  (hidden comment: CRCW04021K00FKED)
R38  ValueDisplayed: 68  [0805_HV]  (hidden comment: HPCR0805J68R0KT)
R39  ValueDisplayed: 68  [0805_HV]  (hidden comment: HPCR0805J68R0KT)
R40  ValueDisplayed: 68  [0805_HV]  (hidden comment: HPCR0805J68R0KT)
R41  ValueDisplayed: 1.00k  [0402]  (hidden comment: CRCW04021K00FKED)
R42  ValueDisplayed: 68  [0805_HV]  (hidden comment: HPCR0805J68R0KT)
R43  ValueDisplayed: 68  [0805_HV]  (hidden comment: HPCR0805J68R0KT)
R44  ValueDisplayed: 68  [0805_HV]  (hidden comment: HPCR0805J68R0KT)
R45  ValueDisplayed: 68  [0805_HV]  (hidden comment: HPCR0805J68R0KT)
R46  ValueDisplayed: 68  [0805_HV]  (hidden comment: HPCR0805J68R0KT)
R47  ValueDisplayed: 68  [0805_HV]  (hidden comment: HPCR0805J68R0KT)
R48  ValueDisplayed: 68  [0805_HV]  (hidden comment: HPCR0805J68R0KT)
R49  ValueDisplayed: 68  [0805_HV]  (hidden comment: HPCR0805J68R0KT)
R50  ValueDisplayed: 68  [0805_HV]  (hidden comment: HPCR0805J68R0KT)
R51  ValueDisplayed: 1.00k  [0402]  (hidden comment: CRCW04021K00FKED)
R52  ValueDisplayed: 68  [0805_HV]  (hidden comment: HPCR0805J68R0KT)
R53  ValueDisplayed: 68  [0805_HV]  (hidden comment: HPCR0805J68R0KT)
R54  ValueDisplayed: 68  [0805_HV]  (hidden comment: HPCR0805J68R0KT)
R55  ValueDisplayed: 68  [0805_HV]  (hidden comment: HPCR0805J68R0KT)
R56  ValueDisplayed: 68  [0805_HV]  (hidden comment: HPCR0805J68R0KT)
R57  ValueDisplayed: 68  [0805_HV]  (hidden comment: HPCR0805J68R0KT)
R58  ValueDisplayed: 68  [0805_HV]  (hidden comment: HPCR0805J68R0KT)
R59  ValueDisplayed: 68  [0805_HV]  (hidden comment: HPCR0805J68R0KT)
R60  ValueDisplayed: 68  [0805_HV]  (hidden comment: HPCR0805J68R0KT)
R61  ValueDisplayed: 1.00k  [0402]  (hidden comment: CRCW04021K00FKED)
R62  ValueDisplayed: 68  [0805_HV]  (hidden comment: HPCR0805J68R0KT)
R63  ValueDisplayed: 68  [0805_HV]  (hidden comment: HPCR0805J68R0KT)
R64  ValueDisplayed: 68  [0805_HV]  (hidden comment: HPCR0805J68R0KT)
R65  ValueDisplayed: 1.00k  [0402]  (hidden comment: CRCW04021K00FKED)
R66  ValueDisplayed: 68  [0805_HV]  (hidden comment: HPCR0805J68R0KT)
R67  ValueDisplayed: 68  [0805_HV]  (hidden comment: HPCR0805J68R0KT)
R68  ValueDisplayed: 68  [0805_HV]  (hidden comment: HPCR0805J68R0KT)
R69  ValueDisplayed: 68  [0805_HV]  (hidden comment: HPCR0805J68R0KT)
R70  ValueDisplayed: 68  [0805_HV]  (hidden comment: HPCR0805J68R0KT)
R71  ValueDisplayed: 68  [0805_HV]  (hidden comment: HPCR0805J68R0KT)
R72  ValueDisplayed: 68  [0805_HV]  (hidden comment: HPCR0805J68R0KT)
R73  ValueDisplayed: 68  [0805_HV]  (hidden comment: HPCR0805J68R0KT)
R74  ValueDisplayed: 68  [0805_HV]  (hidden comment: HPCR0805J68R0KT)
R75  ValueDisplayed: 1.00k  [0402]  (hidden comment: CRCW04021K00FKED)
R76  ValueDisplayed: 68  [0805_HV]  (hidden comment: HPCR0805J68R0KT)
R77  ValueDisplayed: 68  [0805_HV]  (hidden comment: HPCR0805J68R0KT)
R78  ValueDisplayed: 68  [0805_HV]  (hidden comment: HPCR0805J68R0KT)
R79  ValueDisplayed: 511  [0402]  (hidden comment: CRCW0402511RFKED)
R80  ValueDisplayed: 68  [0805_HV]  (hidden comment: HPCR0805J68R0KT)
R81  ValueDisplayed: 68  [0805_HV]  (hidden comment: HPCR0805J68R0KT)
R82  ValueDisplayed: 68  [0805_HV]  (hidden comment: HPCR0805J68R0KT)
R83  ValueDisplayed: 1.00k  [0402]  (hidden comment: CRCW04021K00FKED)
R84  ValueDisplayed: 68  [0805_HV]  (hidden comment: HPCR0805J68R0KT)
R85  ValueDisplayed: 68  [0805_HV]  (hidden comment: HPCR0805J68R0KT)
R86  ValueDisplayed: 68  [0805_HV]  (hidden comment: HPCR0805J68R0KT)
R87  ValueDisplayed: 68  [0805_HV]  (hidden comment: HPCR0805J68R0KT)
R90  ValueDisplayed: 1.00k  [0402]  (hidden comment: CRCW04021K00FKED)
R100  ValueDisplayed: 1.00k  [0402]  (hidden comment: CRCW04021K00FKED)
R104  ValueDisplayed: 1.00k  [0402]  (hidden comment: CRCW04021K00FKED)
R114  ValueDisplayed: 1.00k  [0402]  (hidden comment: CRCW04021K00FKED)
R121  ValueDisplayed: 3.3k  [0402]  (hidden comment: CRCW04023K30JNED)
R122  ValueDisplayed: 3.3k  [0402]  (hidden comment: CRCW04023K30JNED)
R126  ValueDisplayed: 1.00k  [0402]  (hidden comment: CRCW04021K00FKED)
R128  ValueDisplayed: 1.00k  [0402]  (hidden comment: CRCW04021K00FKED)
R132  ValueDisplayed: 1.00k  [0402]  (hidden comment: CRCW04021K00FKED)
R135  ValueDisplayed: 1.00k  [0402]  (hidden comment: CRCW04021K00FKED)
R136  ValueDisplayed: 10M  [0603]  (hidden comment: CRCW060310M0JNEA)
R137  ValueDisplayed: 10M  [0603]  (hidden comment: CRCW060310M0JNEA)
R138  ValueDisplayed: 1.00k  [0402]  (hidden comment: CRCW04021K00FKED)
R139  ValueDisplayed: 1.00k  [0402]  (hidden comment: CRCW04021K00FKED)
R140  ValueDisplayed: 0  [0402]  (hidden comment: CRCW04020000Z0ED)
R144  ValueDisplayed: 10.0k  [0402]  (hidden comment: CRCW040210K0FKED)
R145  ValueDisplayed: 1.0k  [0402]  (hidden comment: CRCW04021K00JNED)
R147  ValueDisplayed: 10.0k  [0402]  (hidden comment: CRCW040210K0FKED)
R148  ValueDisplayed: 1.0k  [0402]  (hidden comment: CRCW04021K00JNED)
R149  ValueDisplayed: 1.0k  [0402]  (hidden comment: CRCW04021K00JNED)
R150  ValueDisplayed: 1.0k  [0402]  (hidden comment: CRCW04021K00JNED)
R151  ValueDisplayed: 1.0k  [0402]  (hidden comment: CRCW04021K00JNED)
R152  ValueDisplayed: 10.0k  [0402]  (hidden comment: CRCW040210K0FKED)
R153  ValueDisplayed: 1.0k  [0402]  (hidden comment: CRCW04021K00JNED)
R154  ValueDisplayed: 100  [2010]  (hidden comment: CRCW2010100RFKEF)
R155  ValueDisplayed: 200  [2010]  (hidden comment: CRCW2010200RFKEF)
R156  ValueDisplayed: 10.0k  [0402]  (hidden comment: CRCW040210K0FKED)
R157  ValueDisplayed: 1.0k  [0402]  (hidden comment: CRCW04021K00JNED)
R158  ValueDisplayed: 10.0k  [0402]  (hidden comment: CRCW040210K0FKED)
R159  ValueDisplayed: 1.0k  [0402]  (hidden comment: CRCW04021K00JNED)
R162  ValueDisplayed: 10.0k  [0402]  (hidden comment: CRCW040210K0FKED)
R164  ValueDisplayed: 1.0k  [0402]  (hidden comment: CRCW04021K00JNED)
R165  ValueDisplayed: 1.0k  [0402]  (hidden comment: CRCW04021K00JNED)
R177  ValueDisplayed: 0  [0603]  (hidden comment: RC0603JR-070RL)
R178  ValueDisplayed: 51  [0603]  (hidden comment: CRCW060351R0JNEA)
R179  ValueDisplayed: 0  [0603]  (hidden comment: ERJ-3GEY0R00V)
R180  ValueDisplayed: 0  [0603]  (hidden comment: ERJ-3GEY0R00V)
R181  ValueDisplayed: 51  [0603]  (hidden comment: CRCW060351R0JNEA)
R182  ValueDisplayed: 0  [0603]  (hidden comment: RC0603JR-070RL)
R184  ValueDisplayed: 510  [0603]  (hidden comment: CRCW0603510RJNEA)
R185  ValueDisplayed: 510  [0603]  (hidden comment: CRCW0603510RJNEA)
R186  ValueDisplayed: 1.00k  [0603]  (hidden comment: ERJ-3EKF1001V)
R187  ValueDisplayed: 1.00k  [0603]  (hidden comment: ERJ-3EKF1001V)
R188  ValueDisplayed: 510  [0603]  (hidden comment: CRCW0603510RJNEA)
R189  ValueDisplayed: 510  [0603]  (hidden comment: CRCW0603510RJNEA)
R190  ValueDisplayed: 0  [0603]  (hidden comment: RC0603JR-070RL)
R191  ValueDisplayed: 51  [0603]  (hidden comment: CRCW060351R0JNEA)
R192  ValueDisplayed: 0  [0603]  (hidden comment: ERJ-3GEY0R00V)
R193  ValueDisplayed: 0  [0603]  (hidden comment: ERJ-3GEY0R00V)
R194  ValueDisplayed: 51  [0603]  (hidden comment: CRCW060351R0JNEA)
R195  ValueDisplayed: 0  [0603]  (hidden comment: RC0603JR-070RL)
R196  ValueDisplayed: 0  [0402]  (hidden comment: CRCW04020000Z0ED)
R197  ValueDisplayed: 0  [0402]  (hidden comment: CRCW04020000Z0ED)
R198  ValueDisplayed: 0  [0402]  (hidden comment: CRCW04020000Z0ED)
R199  ValueDisplayed: 0  [0402]  (hidden comment: CRCW04020000Z0ED)
R200  ValueDisplayed: 0  [0402]  (hidden comment: CRCW04020000Z0ED)
R201  ValueDisplayed: 0  [0402]  (hidden comment: CRCW04020000Z0ED)
R202  ValueDisplayed: 0  [0402]  (hidden comment: CRCW04020000Z0ED)
R203  ValueDisplayed: 0  [0402]  (hidden comment: CRCW04020000Z0ED)
R204  ValueDisplayed: 0  [0402]  (hidden comment: CRCW04020000Z0ED)
R205  ValueDisplayed: 0  [0402]  (hidden comment: CRCW04020000Z0ED)
R206  ValueDisplayed: 0  [0402]  (hidden comment: CRCW04020000Z0ED)
R207  ValueDisplayed: 0  [0402]  (hidden comment: CRCW04020000Z0ED)
R208  ValueDisplayed: 10.0k  [0402]  (hidden comment: CRCW040210K0FKED)
R209  ValueDisplayed: 10.0k  [0402]  (hidden comment: CRCW040210K0FKED)
R210  ValueDisplayed: 10.0k  [0402]  (hidden comment: CRCW040210K0FKED)
R211  ValueDisplayed: 10.0k  [0402]  (hidden comment: CRCW040210K0FKED)
R212  ValueDisplayed: 10.0k  [0402]  (hidden comment: CRCW040210K0FKED)
R213  ValueDisplayed: 10.0k  [0402]  (hidden comment: CRCW040210K0FKED)
R214  ValueDisplayed: 10.0k  [0402]  (hidden comment: CRCW040210K0FKED)
R215  ValueDisplayed: 100k  [0402]  (hidden comment: CRCW0402100KFKED)
R216  ValueDisplayed: 10.0k  [0402]  (hidden comment: CRCW040210K0FKED)
R217  ValueDisplayed: 10.0k  [0402]  (hidden comment: CRCW040210K0FKED)
R218  ValueDisplayed: 10.0k  [0402]  (hidden comment: CRCW040210K0FKED)
R219  ValueDisplayed: 10.0k  [0402]  (hidden comment: CRCW040210K0FKED)
R220  ValueDisplayed: 10.0k  [0402]  (hidden comment: CRCW040210K0FKED)
R221  ValueDisplayed: 10.0k  [0402]  (hidden comment: CRCW040210K0FKED)
R222  ValueDisplayed: 10.0k  [0402]  (hidden comment: CRCW040210K0FKED)
R223  ValueDisplayed: 10.0k  [0402]  (hidden comment: CRCW040210K0FKED)
R224  ValueDisplayed: 10.0k  [0402]  (hidden comment: CRCW040210K0FKED)
R257  ValueDisplayed: 100k  [0402]  (hidden comment: CRCW0402100KFKED)
RT1  value 10k  [DYA0002A-MFG]  (hidden comment: TMP6131DYAT)
RT2  value 10k  [DYA0002A-MFG]  (hidden comment: TMP6131DYAT)
RT3  value 10k  [DYA0002A-MFG]  (hidden comment: TMP6131DYAT)
RT4  value 10k  [DYA0002A-MFG]  (hidden comment: TMP6131DYAT)
U1  BQ78706PAP  [PAP0064N-MFG]
U2  TMUX1308PWR  [PW0016A-MFG]
U3  TMUX1308PWR  [PW0016A-MFG]

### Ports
CELL0 (bidir), CELL1 (bidir), CELL2 (bidir), CELL3 (bidir), CELL4 (bidir), CELL5 (bidir), CELL6 (bidir), CELL7 (bidir), CELL8 (bidir), CELL9 (bidir), CELL10 (bidir), CELL11 (bidir), CELL12 (bidir), CELL13 (bidir), CELL14 (bidir), CELL15 (bidir), CELL16 (bidir), CELL17 (bidir), CELL18 (bidir), CELL_BB (bidir), COMMH_N_OPT (bidir), COMMH_P_OPT (bidir), COMML_N_OPT (bidir), COMML_P_OPT (bidir), GND, ModuleN (bidir), ModuleP (bidir), NFAULT/GPIO2 (bidir), RX/GPIO0 (bidir), TS1 (bidir), TS2 (bidir), TS3 (bidir), TS4 (bidir), TS5 (bidir), TS6 (bidir), TS7 (bidir), TS8 (bidir), TS9 (bidir), TS10 (bidir), TS11 (bidir), TS12 (bidir), TS13 (bidir), TS14 (bidir), TX/GPIO1 (bidir)

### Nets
GND: C6.2 C9.2 C12.2 C18.1 C20.2 C24.2 C26.1 C28.2 C32.2 C38.1 C40.2 C43.2 C46.1 C48.2 C51.2 C55.1 C57.2 C60.2 C64.1 C66.2 C70.2 C78.2 C83.2 C87.2 C92.2 C100.2 C103.2 C107.2 C108.2 C109.2 C110.2 C111.2 C112.2 C113.2 C114.2 C115.1 C116.2 C117.2 C118.2 C119.2 C120.2 C121.2 C122.2 C123.2 C124.2 C125.1 C126.2 C127.2 C128.2 C129.2 C130.2 C131.2 C132.2 C133.2 C135.1 C136.2 C137.2 C138.2 C140.2 C147.1 C148.2 C149.2 C150.2 C151.2 C152.2 C191.1 D4.2(ANODE) D6.2(A) D7.2(A) D8.2(A) D9.2(A) D10.2(A) D11.3(GND) D12.3(GND) J1.4 J1.6 J1.10 J2.21 J2.25 Q1.2(S) Q2.2(S) R136.1 R137.1 R140.1 R148.1 R151.1 RT1.2 RT2.2 RT3.2 RT4.2 U1.42(VSS) U1.55(REF_VSS) U1.65(EP) U2.6(~{EN}) U2.8(GND) U3.6(~{EN}) U3.8(GND) ; port GND
AVDD: C55.2 C120.1 C140.1 R121.2 R122.2 R215.2 R257.2 U1.49(AVDD) U2.16(VDD) U3.16(VDD)
BAT: C1.2 C26.2 D1.1(K) D9.1(K) R36.2 R204.1 R207.1 U1.1(BAT)
BB: C61.2 C62.1 C67.2 C68.1 C75.2 C76.1 C79.2 C80.1 C84.2 C85.1 C89.2 C90.1 C96.2 C97.1 R79.1 U1.20(BB)
CB0: C93.2 C103.1 R84.2 R85.2 R86.2 R87.2 U1.39(CB0)
CB1: C72.2 C93.1 R69.2 R72.2 R76.2 R80.2 U1.37(CB1)
CB2: C52.2 C72.1 R55.2 R58.2 R62.2 R66.2 U1.35(CB2)
CB3: C34.2 C52.1 R42.2 R45.2 R48.2 R52.2 U1.33(CB3)
CB4: C15.2 C34.1 R27.2 R30.2 R33.2 R38.2 U1.31(CB4)
CB5: C2.2 C15.1 R13.2 R16.2 R20.2 R23.2 U1.29(CB5)
CB6: C2.1 C94.2 R1.2 R4.2 R7.2 R10.2 U1.27(CB6)
CB7: C73.2 C94.1 C97.2 R70.2 R73.2 R77.2 R81.2 U1.25(CB7)
CB8: C53.2 C73.1 C90.2 R56.2 R59.2 R63.2 R67.2 U1.23(CB8)
CB9: C35.2 C53.1 C85.2 R43.2 R46.2 R49.2 R53.2 U1.21(CB9)
CB10: C16.2 C35.1 C80.2 R28.2 R31.2 R34.2 R39.2 U1.18(CB10)
CB11: C3.2 C16.1 C76.2 R14.2 R17.2 R21.2 R24.2 U1.16(CB11)
CB12: C3.1 C68.2 C95.2 R2.2 R5.2 R8.2 R11.2 U1.14(CB12)
CB13: C62.2 C74.2 C95.1 R71.2 R74.2 R78.2 R82.2 R196.2 U1.12(CB13)
CB14: C54.2 C74.1 R57.2 R60.2 R64.2 R68.2 R196.1 R202.2 U1.10(CB14)
CB15: C36.2 C54.1 R44.2 R47.2 R50.2 R54.2 R197.2 R202.1 U1.8(BAT)
CB16: C17.2 C36.1 R29.2 R32.2 R35.2 R40.2 R197.1 R203.2 U1.6(BAT)
CB17: C4.2 C17.1 R15.2 R18.2 R22.2 R25.2 R198.2 R203.1 U1.4(BAT)
CB18: C1.1 C4.1 D10.1(K) R3.2 R6.2 R9.2 R12.2 R198.1 R204.2 U1.2(BAT)
CCAP_0: C91.2 C92.1
CCAP_1: C86.2 C87.1
CCAP_2: C82.2 C83.1
CCAP_3: C77.2 C78.1
CCAP_4: C69.2 C70.1
CCAP_5: C65.2 C66.1
CCAP_6: C59.2 C60.1
CCAP_7: C56.2 C57.1
CCAP_8: C50.2 C51.1
CCAP_9: C47.2 C48.1
CCAP_10: C42.2 C43.1
CCAP_11: C39.2 C40.1
CCAP_12: C31.2 C32.1
CCAP_13: C27.2 C28.1
CCAP_14: C23.2 C24.1
CCAP_15: C19.2 C20.1
CCAP_16: C11.2 C12.1
CCAP_17: C8.2 C9.1
CCAP_18: C5.2 C6.1
CCAP_BB: C99.2 C100.1
CELL0: C91.1 D4.1(CATHODE) D5.2(ANODE) J2.10 R84.1 R85.1 R86.1 R87.1 R139.1 ; port CELL0
CELL1: C86.1 D5.1(CATHODE) J2.31 R69.1 R72.1 R76.1 R80.1 R138.1 ; port CELL1
CELL2: C82.1 J2.11 R55.1 R58.1 R62.1 R66.1 R135.1 ; port CELL2
CELL3: C77.1 J2.32 R42.1 R45.1 R48.1 R52.1 R132.1 ; port CELL3
CELL4: C69.1 J2.12 R27.1 R30.1 R33.1 R38.1 R128.1 ; port CELL4
CELL5: C65.1 J2.33 R13.1 R16.1 R20.1 R23.1 R126.1 ; port CELL5
CELL6: C59.1 J2.13 R1.1 R4.1 R7.1 R10.1 R114.1 ; port CELL6
CELL7: C56.1 J2.34 R70.1 R73.1 R77.1 R81.1 R104.1 ; port CELL7
CELL8: C50.1 J2.14 R56.1 R59.1 R63.1 R67.1 R100.1 ; port CELL8
CELL9: C47.1 J2.35 R43.1 R46.1 R49.1 R53.1 R90.1 ; port CELL9
CELL10: C42.1 J2.36 R28.1 R31.1 R34.1 R39.1 R83.1 ; port CELL10
CELL11: C39.1 J2.16 R14.1 R17.1 R21.1 R24.1 R75.1 ; port CELL11
CELL12: C31.1 J2.37 R2.1 R5.1 R8.1 R11.1 R65.1 ; port CELL12
CELL13: C27.1 J2.17 R61.1 R71.1 R74.1 R78.1 R82.1 ; port CELL13
CELL14: C23.1 J2.38 R51.1 R57.1 R60.1 R64.1 R68.1 ; port CELL14
CELL15: C19.1 J2.18 R41.1 R44.1 R47.1 R50.1 R54.1 ; port CELL15
CELL16: C11.1 J2.39 R29.1 R32.1 R35.1 R37.1 R40.1 ; port CELL16
CELL17: C8.1 D7.1(K) J2.19 R15.1 R18.1 R22.1 R25.1 R26.1 ; port CELL17
CELL18: C5.1 D8.1(K) J2.40 R3.1 R6.1 R9.1 R12.1 R19.1 ; port CELL18
CELL_BB: C99.1 J2.15 R79.2 ; port CELL_BB
COMHN: C150.1 R193.1 U1.45(COMHN)
COMHP: C151.1 R180.1 U1.46(COMHP)
COMLN: C149.1 R192.2 U1.44(COMLN)
COMLP: C152.1 R179.2 U1.43(COMLP)
COMMH_N: R187.1 R189.1 R193.2 R194.1
COMMH_N_OPT: J4.2 R195.2 ; port COMMH_N_OPT
COMMH_P: R180.2 R181.1 R185.2 R187.2
COMMH_P_OPT: J4.1 R182.2 ; port COMMH_P_OPT
COMML_N: R186.1 R188.1 R191.2 R192.1
COMML_N_OPT: J3.2 R190.1 ; port COMML_N_OPT
COMML_P: R178.2 R179.1 R184.2 R186.2
COMML_P_OPT: J3.1 R177.1 ; port COMML_P_OPT
DVDD: C38.2 Q1.1(G) R136.2 U1.41(DVDD_CAP)
GPIO3: C119.1 R153.1 U1.64(GPIO3)
GPIO4: C124.1 R157.1 U1.63(GPIO4)
GPIO5: C129.1 R159.1 U1.62(GPIO5)
GPIO6: C133.1 R165.1 U1.61(GPIO6)
GPIO7: C115.2 R149.1 U1.60(GPIO7)
GPIO7_R: R149.2 U2.3(D)
GPIO8: C135.2 R164.1 U1.59(GPIO8)
GPIO8_R: R164.2 U3.3(D)
GPIO9: U1.58(GPIO9) U2.11(A0) U3.11(A0)
GPIO10: U1.57(GPIO10) U2.10(A1) U3.10(A1)
GPIO11: U1.56(GPIO11) U2.9(A2) U3.9(A2)
LDOIN: C18.2 Q3.3(E) U1.48(LDOIN)
ModuleN: J2.30 R140.2 ; port ModuleN
ModuleP: D6.1(K) J2.20 R36.1 R155.2 ; port ModuleP
ModuleP_L: C125.2 C191.2 Q3.2(C) R154.1
NFAULT/GPIO2: C114.1 Q2.1(G) R137.2 R150.1 R215.1 U1.53(~{FAULT}/GPIO2) ; port NFAULT/GPIO2
NPNB: Q3.1(B) U1.47(NPNB)
REF_CAP: C64.2 U1.54(REF_CAP)
RX/GPIO0: R257.1 U1.51(RX/GPIO0) ; port RX/GPIO0
TS1: C136.1 J2.1 R214.1 U3.5(S5) ; port TS1
TS2: C130.1 J2.22 R213.1 U3.4(S7) ; port TS2
TS3: C126.1 J2.2 R212.1 U3.2(S6) ; port TS3
TS4: C121.1 J2.23 R211.1 U3.1(S4) ; port TS4
TS5: C116.1 J2.3 R210.1 U3.15(S2) ; port TS5
TS6: C111.1 J2.24 R209.1 U3.14(S1) ; port TS6
TS7: C108.1 J2.4 R208.1 U3.13(S0) ; port TS7
TS8: C137.1 J2.5 R221.1 U2.5(S5) ; port TS8
TS9: C131.1 J2.26 R220.1 U2.4(S7) ; port TS9
TS10: C127.1 J2.6 R219.1 U2.2(S6) ; port TS10
TS11: C122.1 J2.27 R218.1 U2.1(S4) ; port TS11
TS12: C117.1 J2.7 R217.1 U2.15(S2) ; port TS12
TS13: C112.1 J2.28 R216.1 U2.14(S1) ; port TS13
TS14: C109.1 J2.8 R224.1 U2.13(S0) ; port TS14
TS15: C138.1 J1.3 R162.1 R165.2
TS16: C132.1 J1.5 R158.1 R159.2
TS17: C128.1 J1.7 R156.1 R157.2 RT1.1
TS18: C123.1 J1.8 R152.1 R153.2 RT2.1
TS19: C118.1 J1.1 R147.1 R150.2 RT3.1
TS20: C113.1 J1.2 R144.1 R145.2 RT4.1
TS_R1: R148.2 R222.1 U3.12(S3)
TS_R2: R151.2 R223.1 U2.12(S3)
TSREF: C46.2 R144.2 R147.2 R152.2 R156.2 R158.2 R162.2 R208.2 R209.2 R210.2 R211.2 R212.2 R213.2 R214.2 R216.2 R217.2 R218.2 R219.2 R220.2 R221.2 R222.2 R223.2 R224.2 U1.50(TSREF)
TX/GPIO1: C110.1 R145.1 U1.52(TX/GPIO1) ; port TX/GPIO1
VC0: C106.2 C107.1 R139.2 U1.40(VC0)
VC1: C105.2 C106.1 R138.2 U1.38(VC1)
VC2: C104.2 C105.1 R135.2 U1.36(VC2)
VC3: C102.2 C104.1 R132.2 U1.34(VC3)
VC4: C101.2 C102.1 R128.2 U1.32(VC4)
VC5: C98.2 C101.1 R126.2 U1.30(VC5)
VC6: C88.2 C98.1 R114.2 U1.28(VC6)
VC7: C81.2 C88.1 C96.1 R104.2 U1.26(VC7)
VC8: C71.2 C81.1 C89.1 R100.2 U1.24(VC8)
VC9: C63.2 C71.1 C84.1 R90.2 U1.22(VC9)
VC10: C58.2 C63.1 C79.1 R83.2 U1.19(VC10)
VC11: C49.2 C58.1 C75.1 R75.2 U1.17(VC11)
VC12: C45.2 C49.1 C67.1 R65.2 U1.15(VC12)
VC13: C37.2 C45.1 C61.1 R61.2 R199.2 U1.13(VC13)
VC14: C30.2 C37.1 R51.2 R199.1 R205.2 U1.11(VC14)
VC15: C22.2 C30.1 R41.2 R200.2 R205.1 U1.9(BAT)
VC16: C14.2 C22.1 R37.2 R200.1 R206.2 U1.7(BAT)
VC17: C7.2 C14.1 R26.2 R201.2 R206.1 U1.5(BAT)
VC18: C7.1 D1.2(A) R19.2 R201.1 R207.2 U1.3(BAT)
NetC147_2: C147.2 R184.1 R188.2
NetC148_1: C148.1 R185.1 R189.2
NetD2_1: D2.1(A) R121.1
NetD2_2: D2.2(K) Q1.3(D)
NetD3_1: D3.1(A) R122.1
NetD3_2: D3.2(K) Q2.3(D)
NetD11_1: D11.1(1_IO) R177.2 R178.1
NetD11_2: D11.2(2_IO) R190.2 R191.1
NetD12_1: D12.1(1_IO) R194.2 R195.1
NetD12_2: D12.2(2_IO) R181.2 R182.1
NetR154_2: R154.2 R155.1

Not connected (* = marked no-connect by the designer): J1 9*; J2 9* 29* 41(MNT_1)* 42(MNT_2)*; U2 7(NC)*; U3 7(NC)*

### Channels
A1: designators end in _A1; ports CELL0=CELL0_A1 CELL1=CELL1_A1 CELL2=CELL2_A1 CELL3=CELL3_A1 CELL4=CELL4_A1 CELL5=CELL5_A1 CELL6=CELL6_A1 CELL7=CELL7_A1 CELL8=CELL8_A1 CELL9=CELL9_A1 CELL10=CELL10_A1 CELL11=CELL11_A1 CELL12=CELL12_A1 CELL13=CELL13_A1 CELL14=CELL14_A1 CELL15=CELL15_A1 CELL16=CELL16_A1 CELL17=CELL17_A1 CELL18=CELL18_A1 CELL_BB=CELL_BB_A1 COMMH_N_OPT=COMMH_N_OPT COMMH_P_OPT=COMMH_P_OPT COMML_N_OPT=COMML_N_OPT COMML_P_OPT=COMML_P_OPT GND=GND ModuleN=ModuleN_A1 ModuleP=ModuleP_A1 NFAULT/GPIO2=NFAULT/GPIO2 RX/GPIO0=RX/GPIO0 TS1=TS1_A1 TS2=TS2_A1 TS3=TS3_A1 TS4=TS4_A1 TS5=TS5_A1 TS6=TS6_A1 TS7=TS7_A1 TS8=TS8_A1 TS9=TS9_A1 TS10=TS10_A1 TS11=TS11_A1 TS12=TS12_A1 TS13=TS13_A1 TS14=TS14_A1 TX/GPIO1=TX/GPIO1
A2: designators end in _A2; ports CELL0=CELL0_A2 CELL1=CELL1_A2 CELL2=CELL2_A2 CELL3=CELL3_A2 CELL4=CELL4_A2 CELL5=CELL5_A2 CELL6=CELL6_A2 CELL7=CELL7_A2 CELL8=CELL8_A2 CELL9=CELL9_A2 CELL10=CELL10_A2 CELL11=CELL11_A2 CELL12=CELL12_A2 CELL13=CELL13_A2 CELL14=CELL14_A2 CELL15=CELL15_A2 CELL16=CELL16_A2 CELL17=CELL17_A2 CELL18=CELL18_A2 CELL_BB=CELL_BB_A2 COMMH_N_OPT=COMMH_N_OPT COMMH_P_OPT=COMMH_P_OPT COMML_N_OPT=COMML_N_OPT COMML_P_OPT=COMML_P_OPT GND=GND ModuleN=ModuleN_A2 ModuleP=ModuleP_A2 NFAULT/GPIO2=NFAULT/GPIO2_A2 RX/GPIO0=RX/GPIO0_A2 TS1=TS1_A2 TS2=TS2_A2 TS3=TS3_A2 TS4=TS4_A2 TS5=TS5_A2 TS6=TS6_A2 TS7=TS7_A2 TS8=TS8_A2 TS9=TS9_A2 TS10=TS10_A2 TS11=TS11_A2 TS12=TS12_A2 TS13=TS13_A2 TS14=TS14_A2 TX/GPIO1=TX/GPIO1_A2
A3: designators end in _A3; ports CELL0=CELL0_A3 CELL1=CELL1_A3 CELL2=CELL2_A3 CELL3=CELL3_A3 CELL4=CELL4_A3 CELL5=CELL5_A3 CELL6=CELL6_A3 CELL7=CELL7_A3 CELL8=CELL8_A3 CELL9=CELL9_A3 CELL10=CELL10_A3 CELL11=CELL11_A3 CELL12=CELL12_A3 CELL13=CELL13_A3 CELL14=CELL14_A3 CELL15=CELL15_A3 CELL16=CELL16_A3 CELL17=CELL17_A3 CELL18=CELL18_A3 CELL_BB=CELL_BB_A3 COMMH_N_OPT=COMMH_N_OPT COMMH_P_OPT=COMMH_P_OPT COMML_N_OPT=COMML_N_OPT COMML_P_OPT=COMML_P_OPT GND=GND ModuleN=ModuleN_A3 ModuleP=ModuleP_A3 NFAULT/GPIO2=NFAULT/GPIO2_A3 RX/GPIO0=RX/GPIO0_A3 TS1=TS1_A3 TS2=TS2_A3 TS3=TS3_A3 TS4=TS4_A3 TS5=TS5_A3 TS6=TS6_A3 TS7=TS7_A3 TS8=TS8_A3 TS9=TS9_A3 TS10=TS10_A3 TS11=TS11_A3 TS12=TS12_A3 TS13=TS13_A3 TS14=TS14_A3 TX/GPIO1=TX/GPIO1_A3
A4: designators end in _A4; ports CELL0=CELL0_A4 CELL1=CELL1_A4 CELL2=CELL2_A4 CELL3=CELL3_A4 CELL4=CELL4_A4 CELL5=CELL5_A4 CELL6=CELL6_A4 CELL7=CELL7_A4 CELL8=CELL8_A4 CELL9=CELL9_A4 CELL10=CELL10_A4 CELL11=CELL11_A4 CELL12=CELL12_A4 CELL13=CELL13_A4 CELL14=CELL14_A4 CELL15=CELL15_A4 CELL16=CELL16_A4 CELL17=CELL17_A4 CELL18=CELL18_A4 CELL_BB=CELL_BB_A4 COMMH_N_OPT=COMMH_N_OPT COMMH_P_OPT=COMMH_P_OPT COMML_N_OPT=COMML_N_OPT COMML_P_OPT=COMML_P_OPT GND=GND ModuleN=ModuleN_A4 ModuleP=ModuleP_A4 NFAULT/GPIO2=NFAULT/GPIO2_A4 RX/GPIO0=RX/GPIO0_A4 TS1=TS1_A4 TS2=TS2_A4 TS3=TS3_A4 TS4=TS4_A4 TS5=TS5_A4 TS6=TS6_A4 TS7=TS7_A4 TS8=TS8_A4 TS9=TS9_A4 TS10=TS10_A4 TS11=TS11_A4 TS12=TS12_A4 TS13=TS13_A4 TS14=TS14_A4 TX/GPIO1=TX/GPIO1_A4

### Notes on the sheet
- Cell balancing
- Cell voltage
- 100mA CB current
- Input ESD protection
- (near C18) Power Cap
- (near R257) R257:100k pullup only for AFE1 in CAN, others short to AVDD
- Status indiation
  1 shutdown: No on
  2 wake and normal: 2 Green
  3 wake and abnormal: 1 green
- USE RB160MM-60TFTR
- Cell temperature
- NPN Power Supply-150V
- 20 Thermistor input with 400ms refresh
  TSx is input to GPIO ADC
  TCx_C is connector input
  TSR1&2 is set >125C/<1k(0.8k) for PTC ERT-J1VG103GA
  TSR1&2 is set <-40C/ <5k(3k) for TMP6131DECR
- 1.Two TMUX populated to sense 2022(2 self test) temp per AFE for full temp using BQ78718.
  2.One TMUX populated to sense 1415(1 self test) temp per AFE for full temp using BQ78706 by GPIO17 and TMUX(GPIO811)
  3.No TMUX populated to sense 11 temp per AFE for half temp using BQ78706(7+1BB) by GPIO18. TS14+TS7 is near to GPIO7/8
- Communication
- 1. TS15~TS20, 3 GND
  2. TS14,TS4, 1 GND
  3. One connector not used 40pin
- Cell channel config
  12*4: short 6 resistors
  13*4: short 5 resistors
  18*3: No shart and SMT BQ79718
- ESD652？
